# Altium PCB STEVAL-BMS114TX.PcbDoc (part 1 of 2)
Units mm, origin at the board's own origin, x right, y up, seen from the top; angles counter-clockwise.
Board outline 75.8 x 95.1 mm, 4 copper layers (Top Layer, Layer 1, Layer 2, Bottom Layer), stack 1.59 mm thick; 304 components, 148 nets, 694 pads, 400 vias.
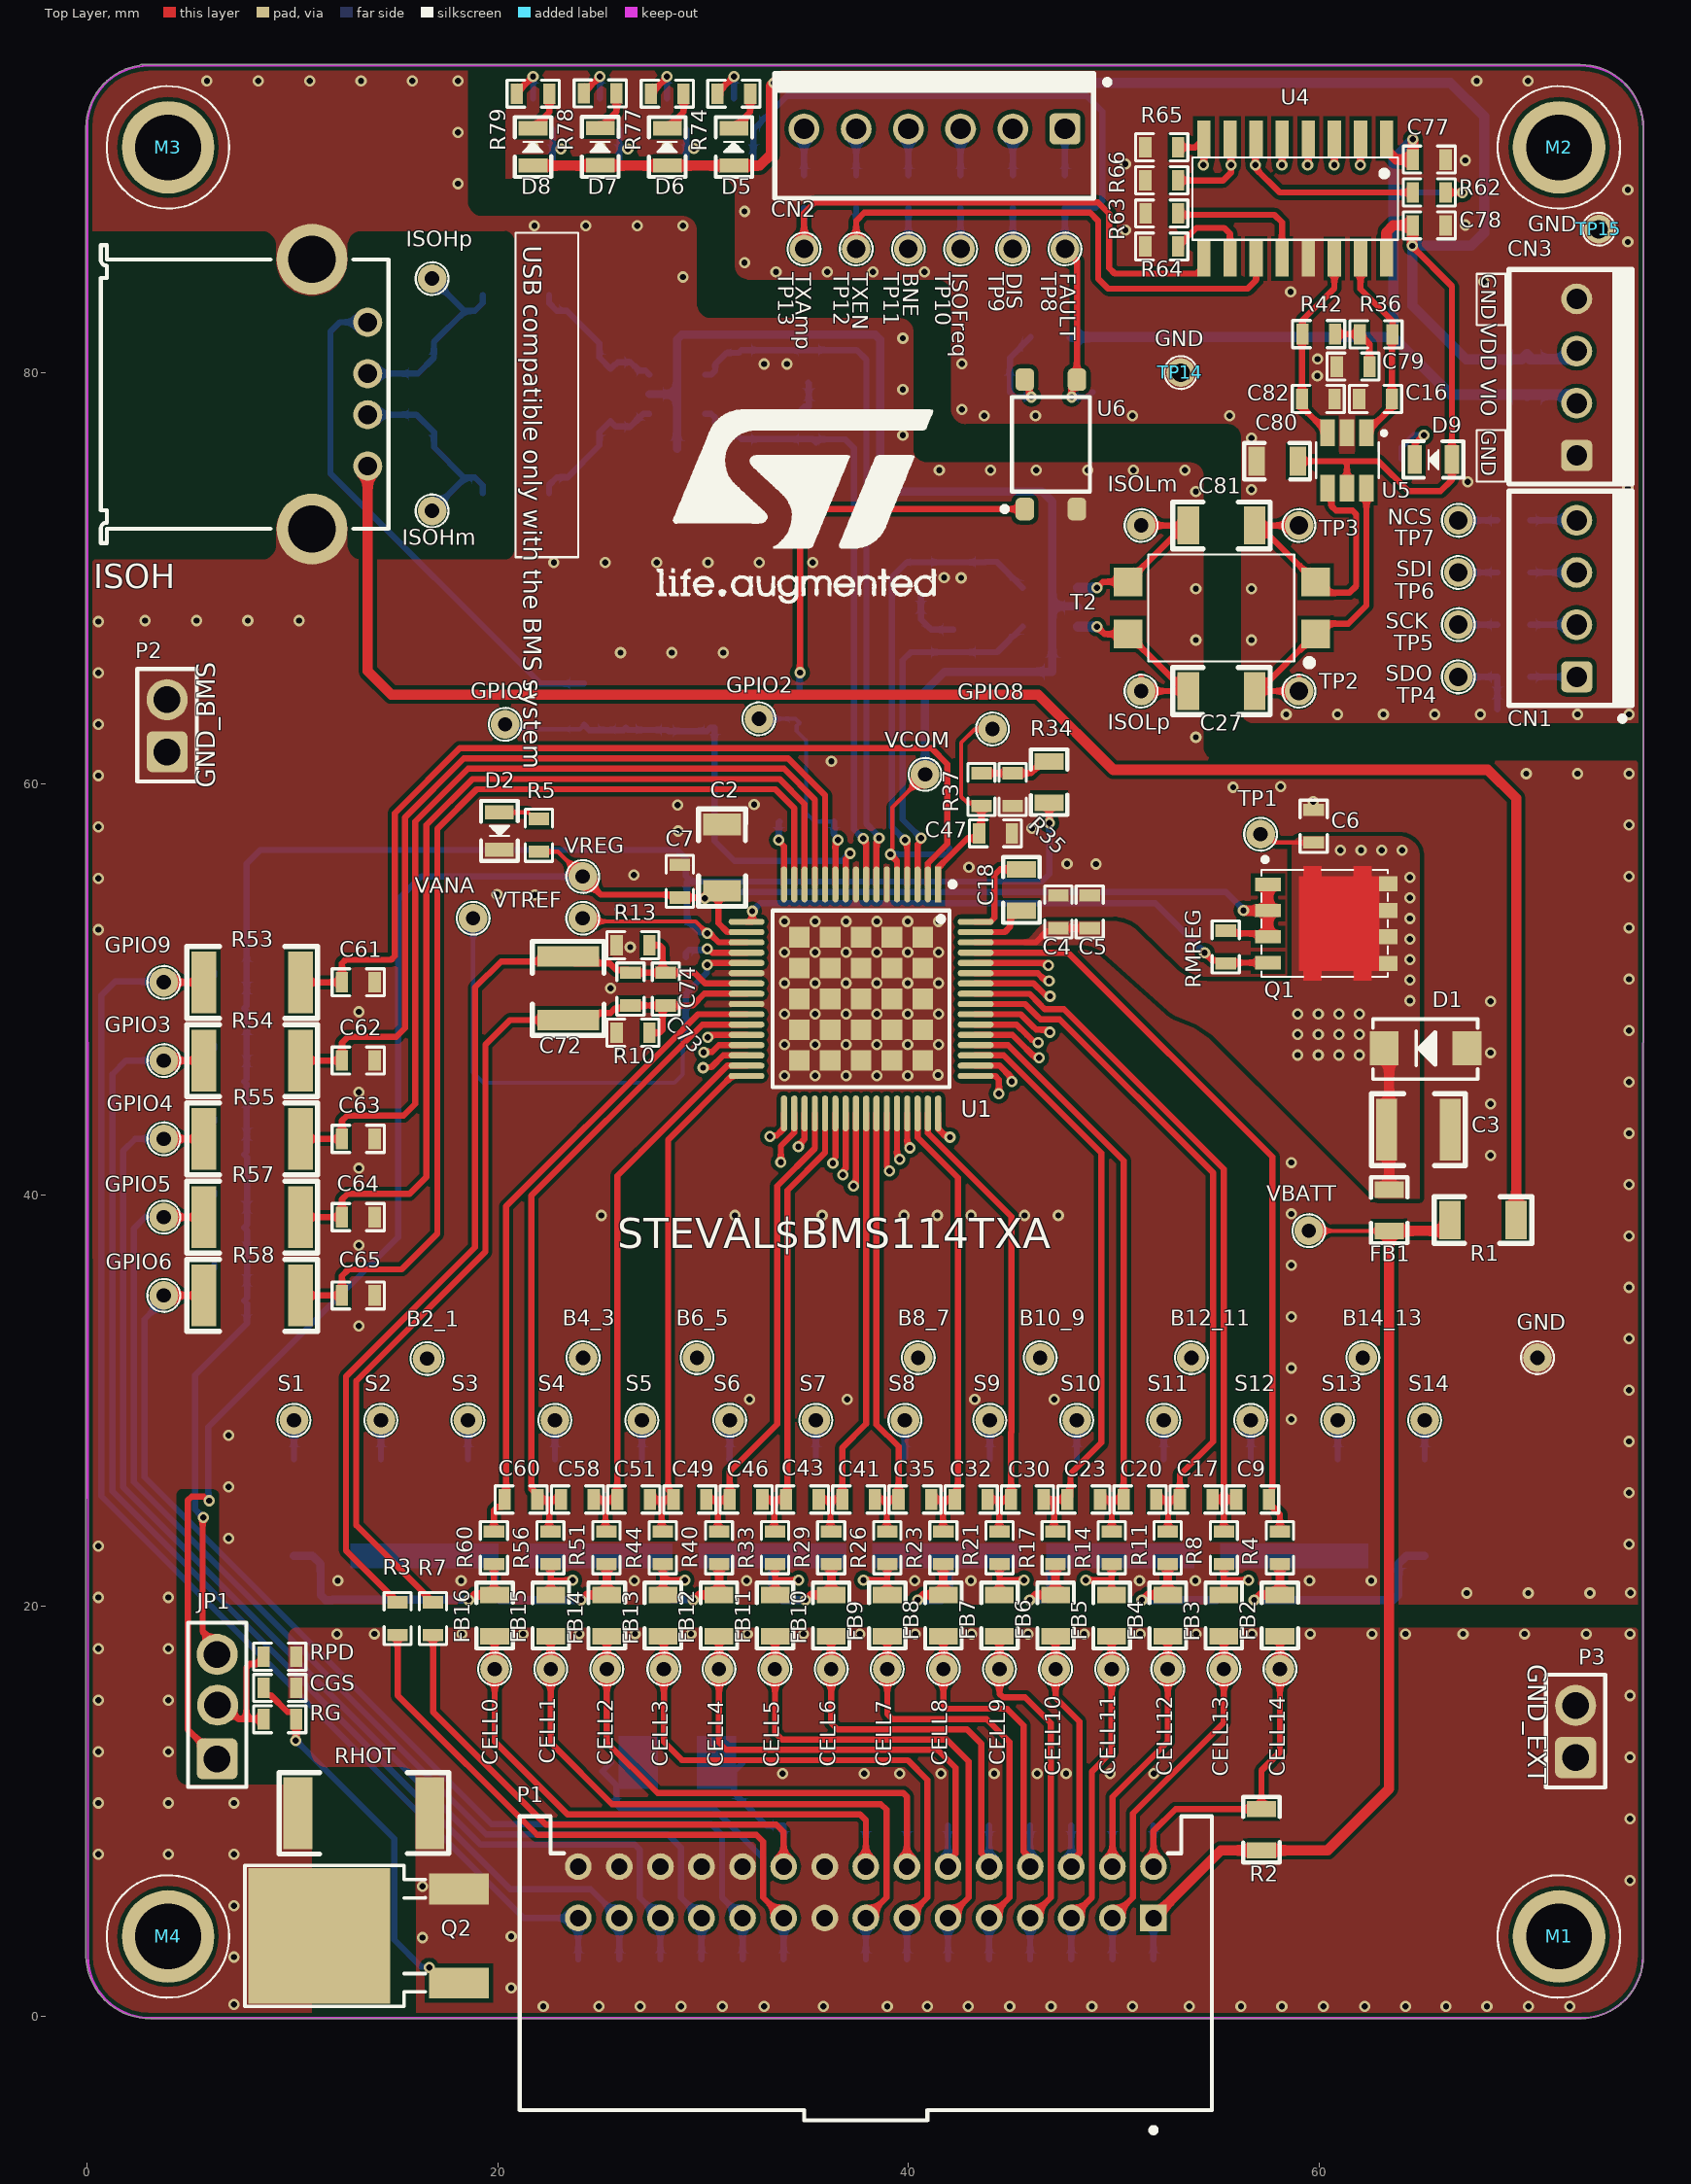
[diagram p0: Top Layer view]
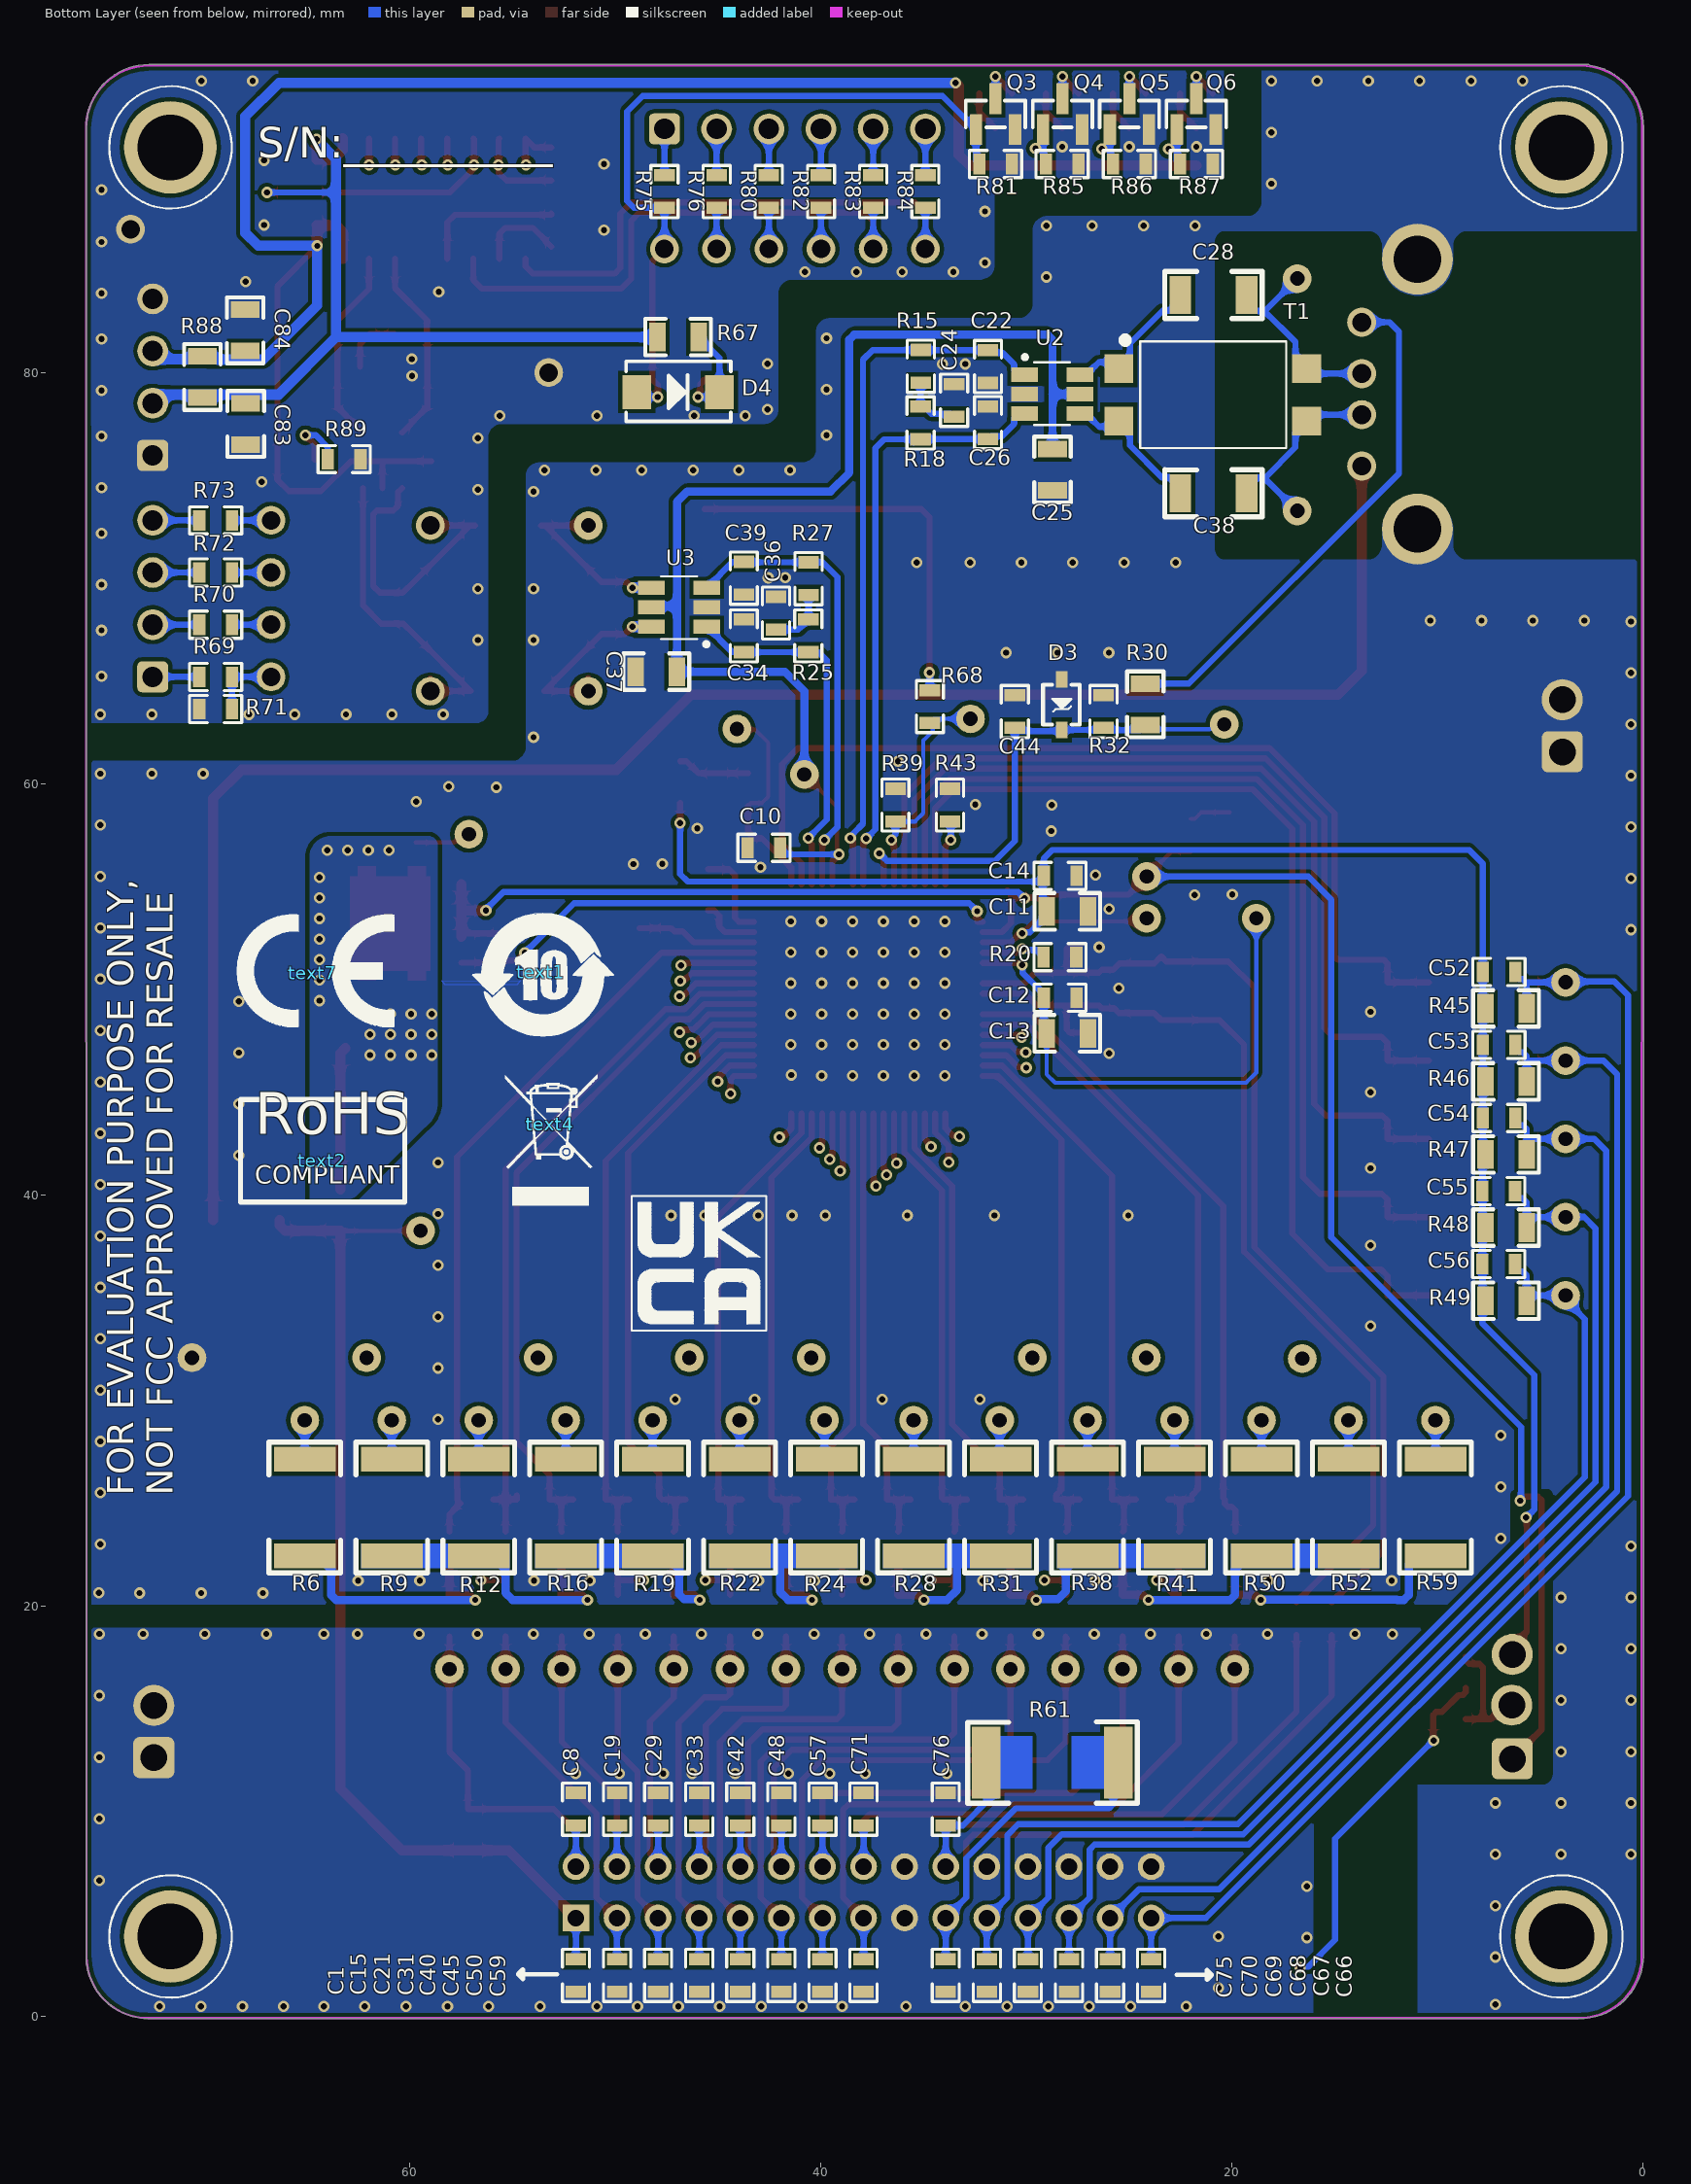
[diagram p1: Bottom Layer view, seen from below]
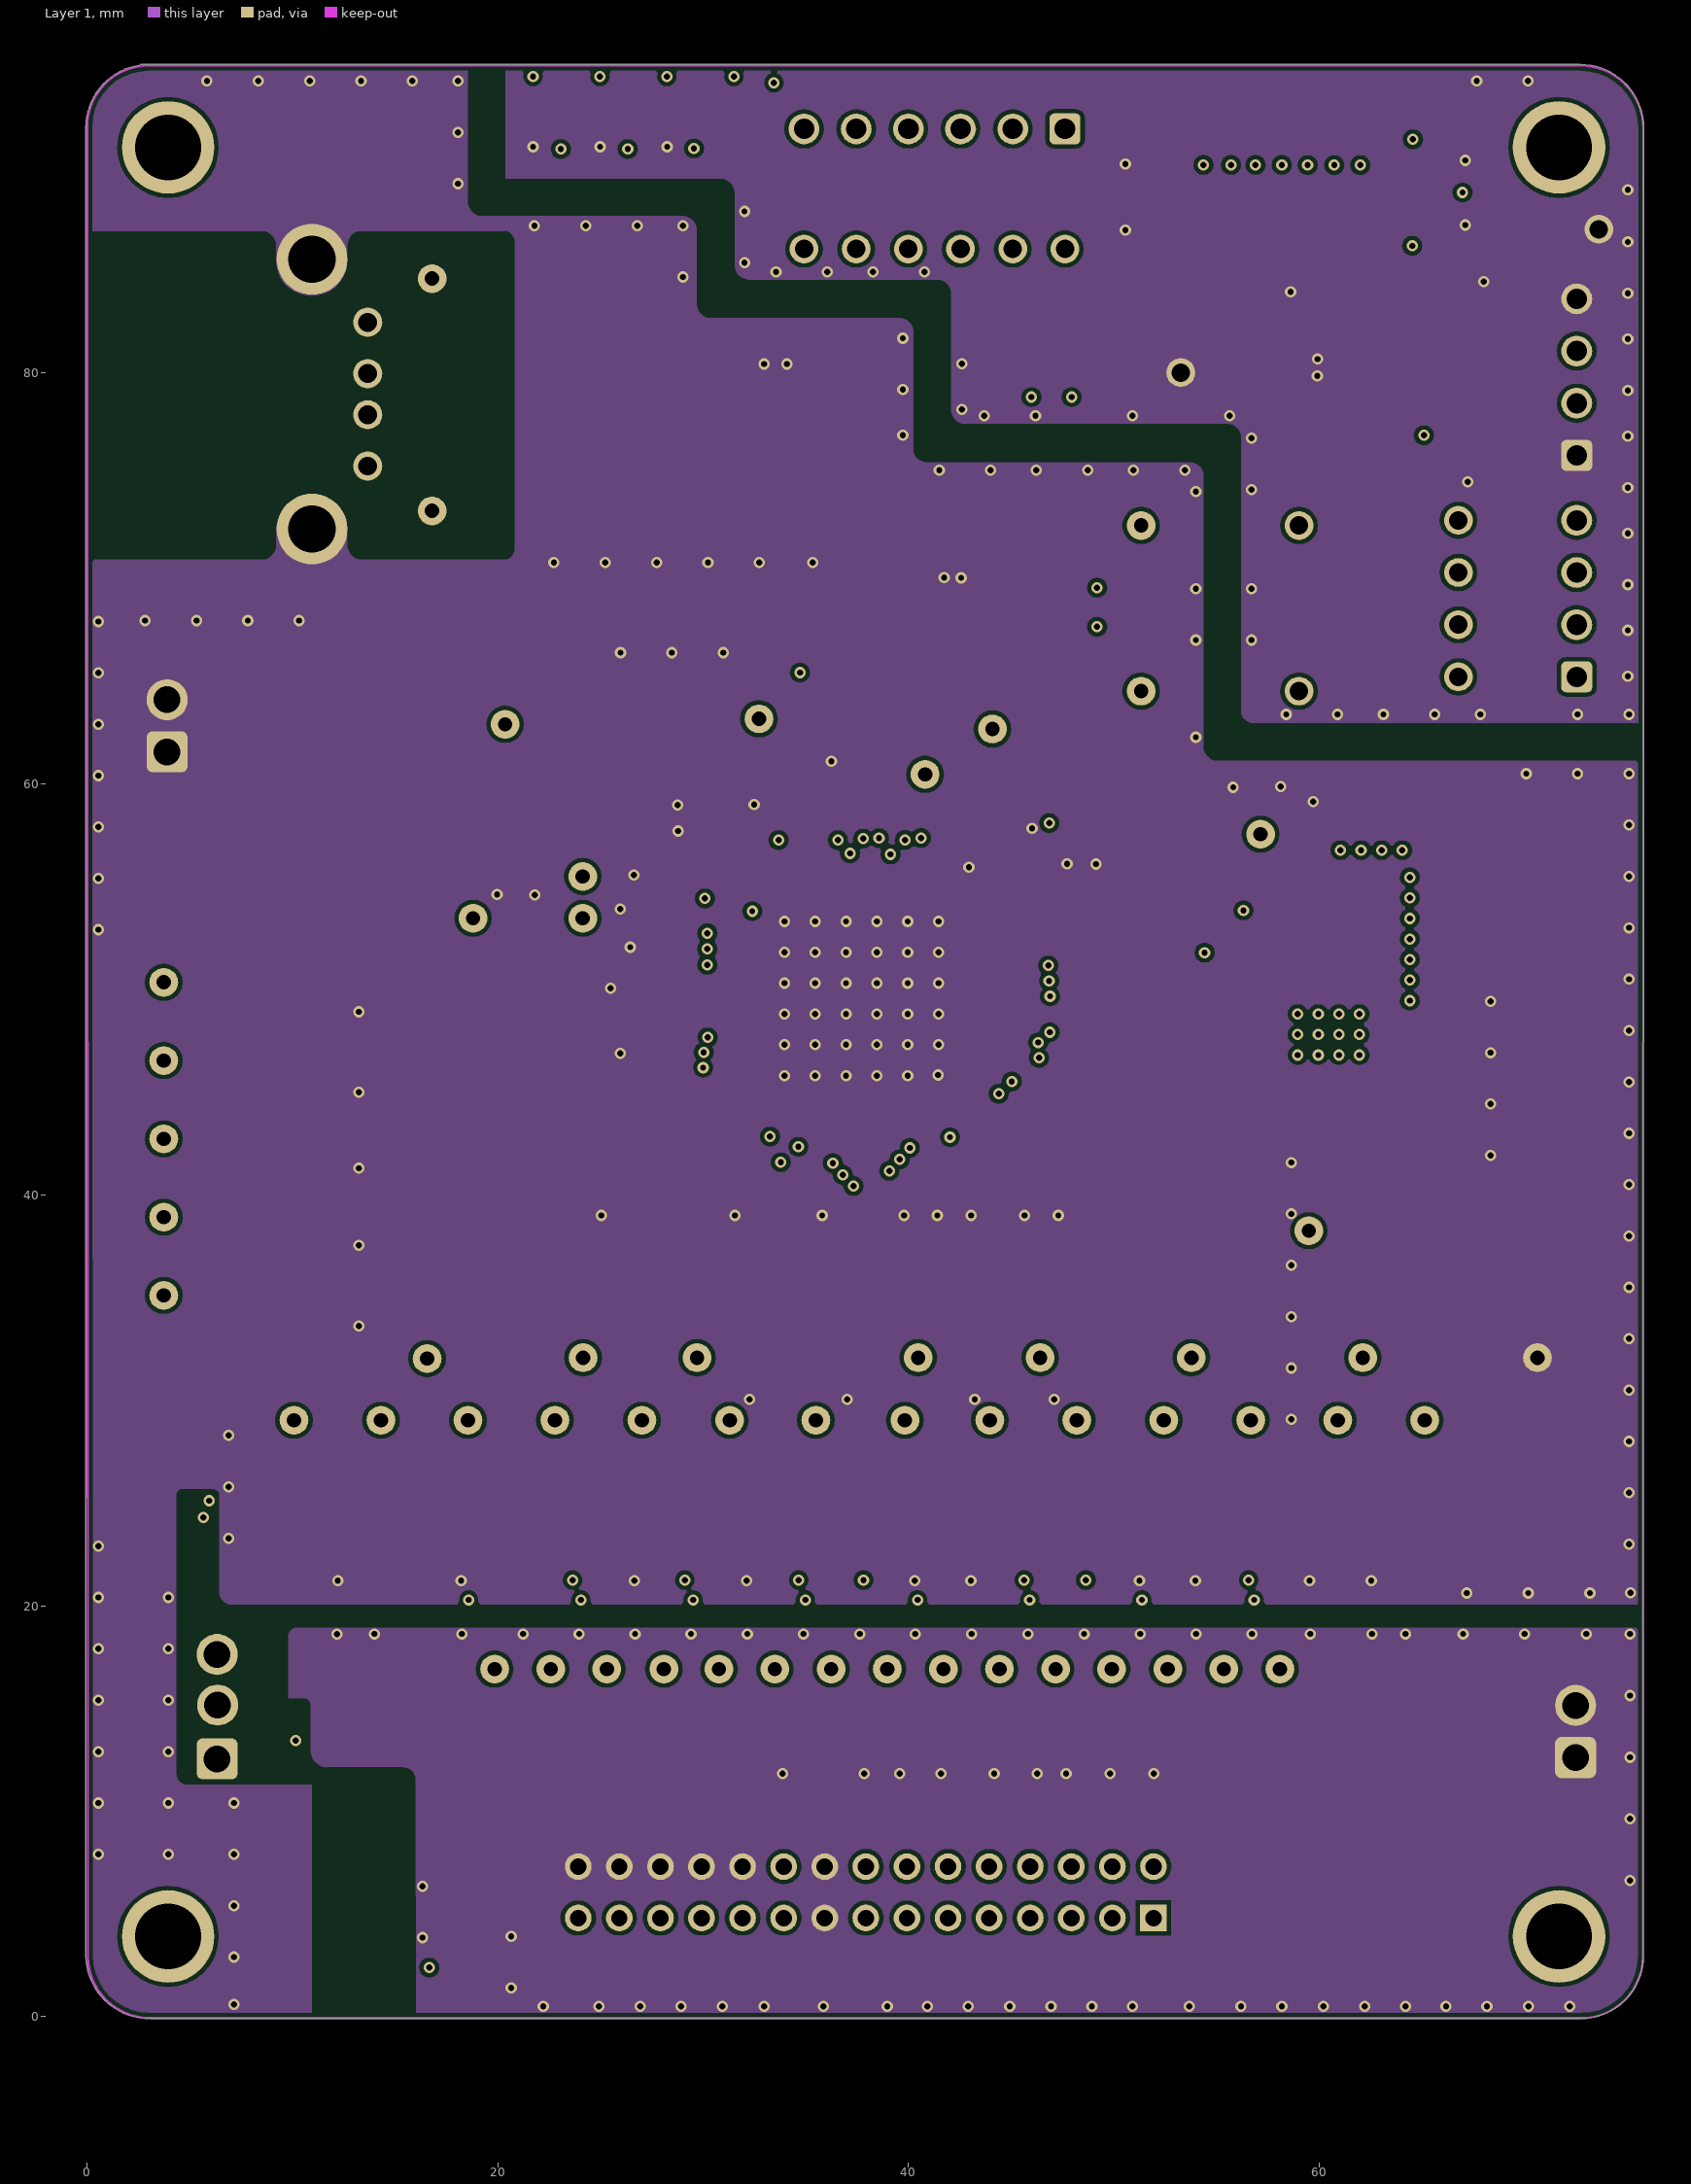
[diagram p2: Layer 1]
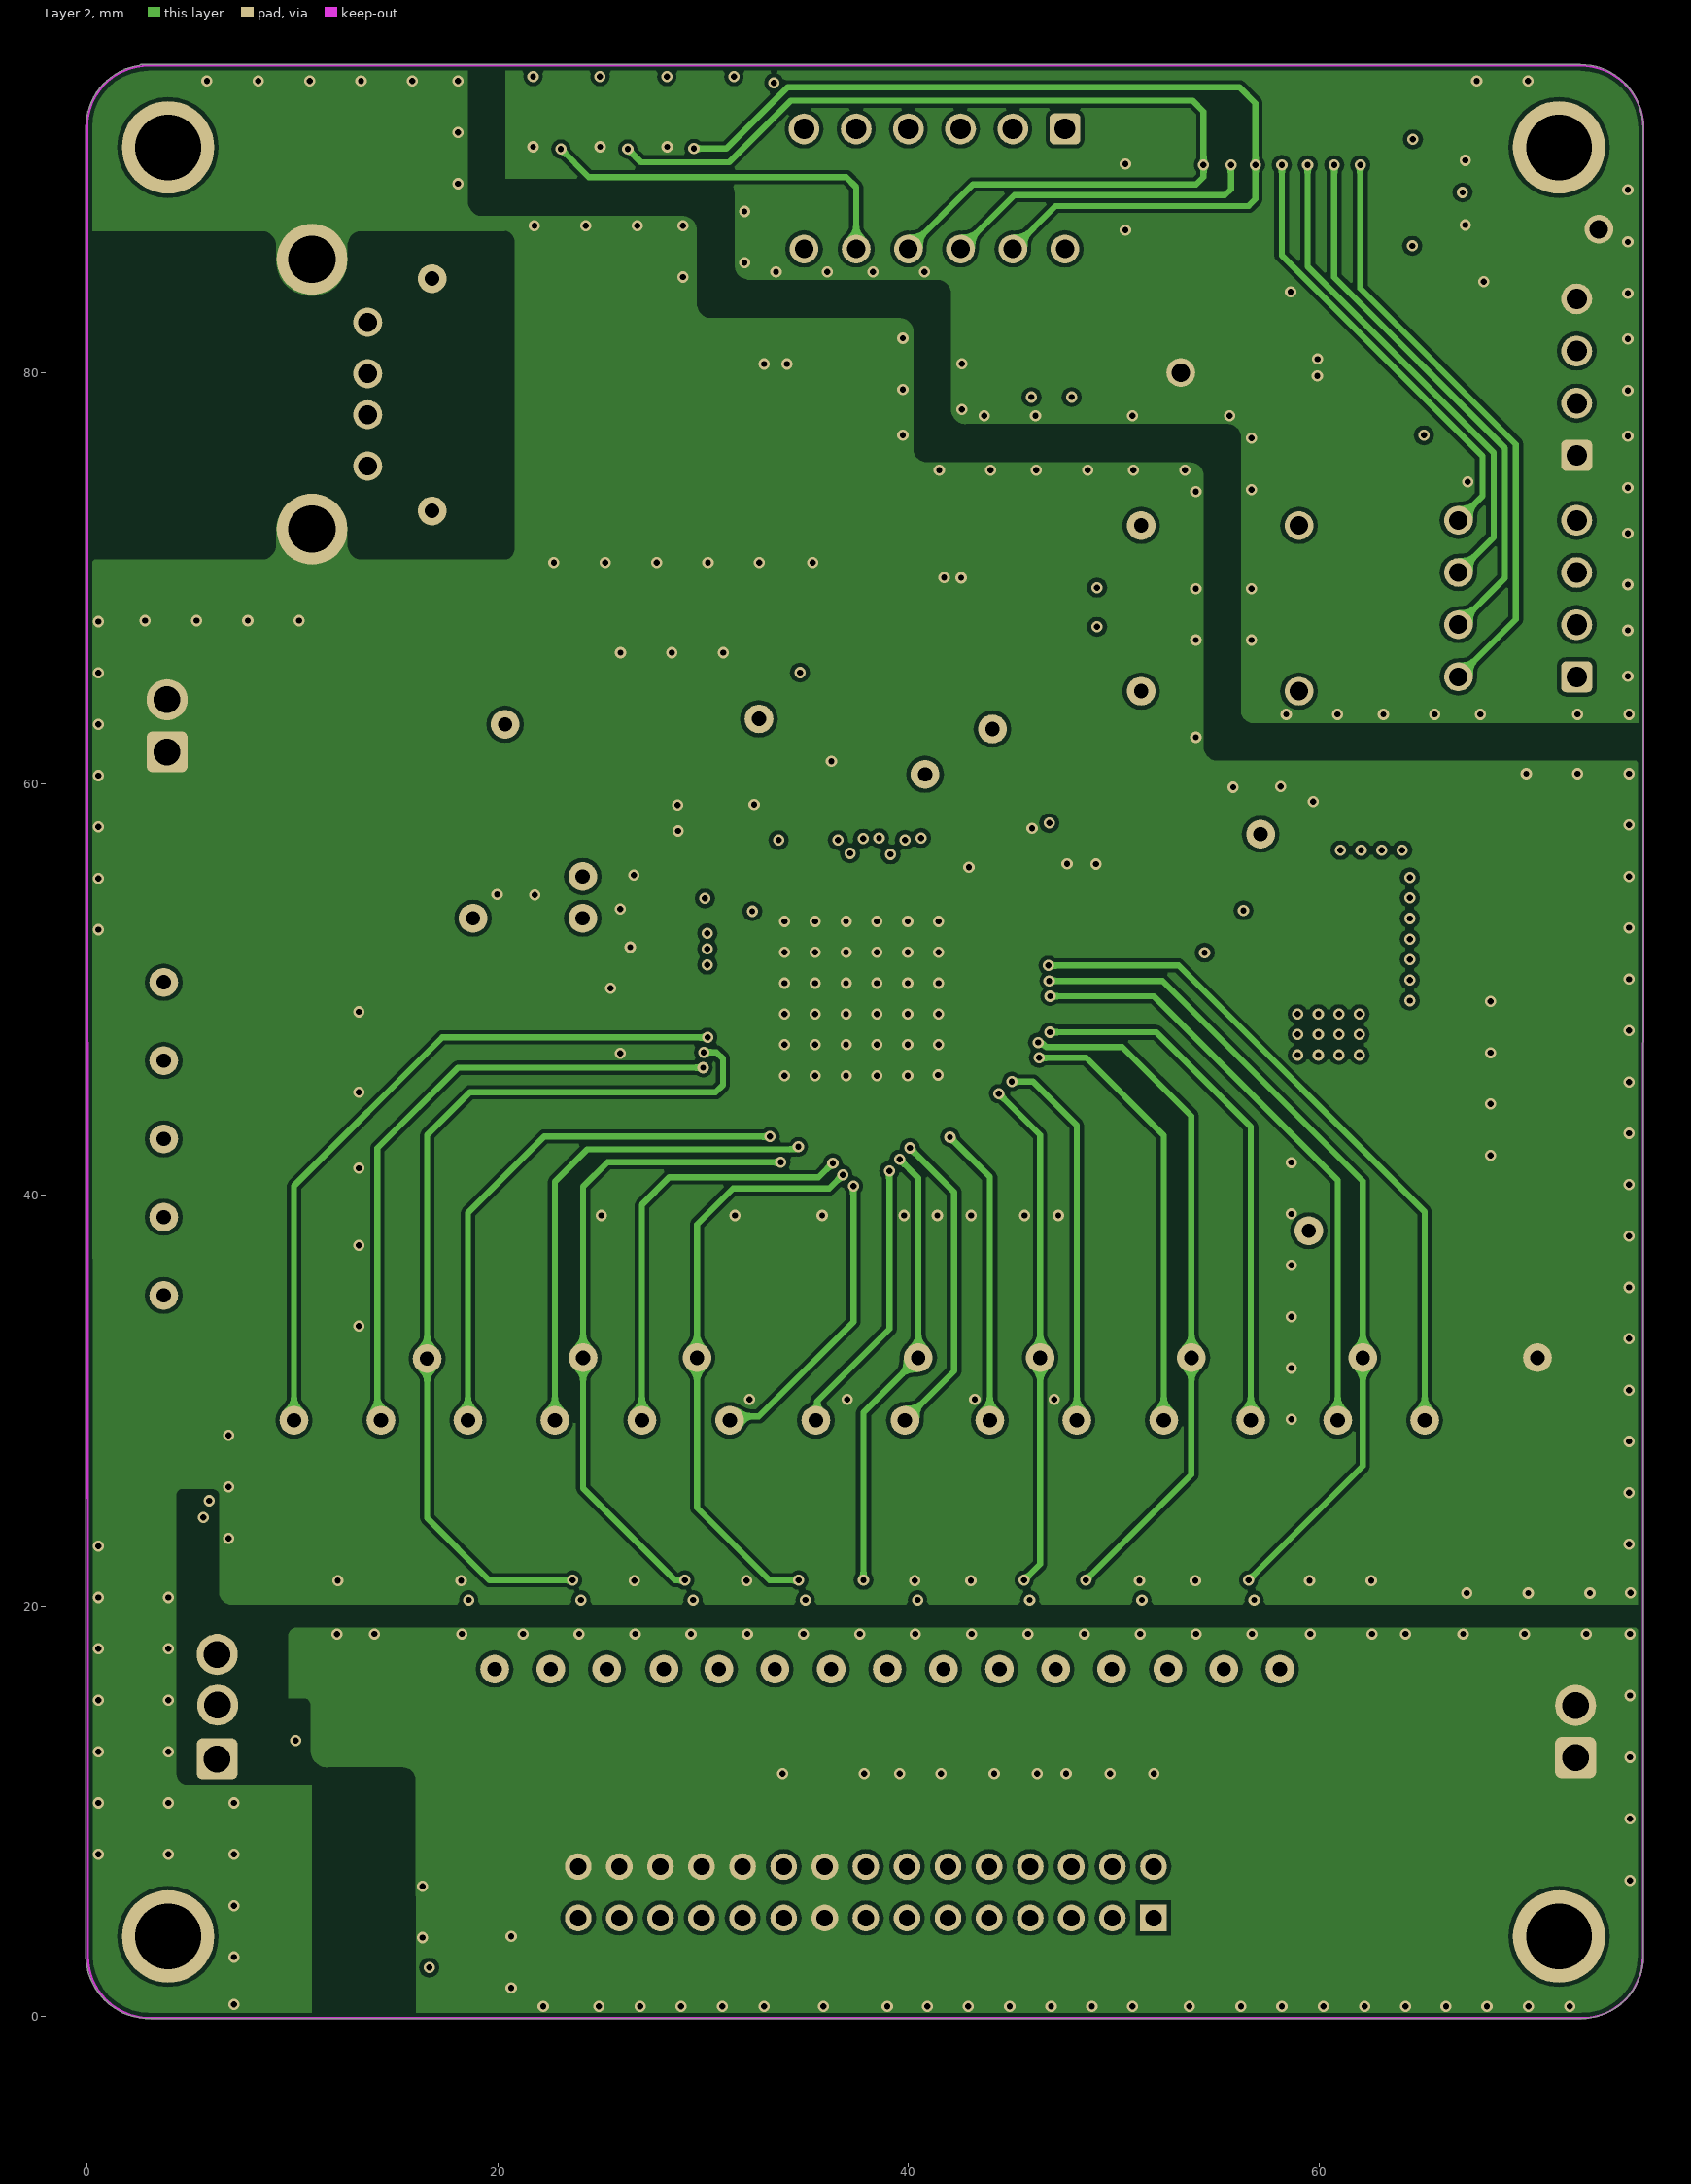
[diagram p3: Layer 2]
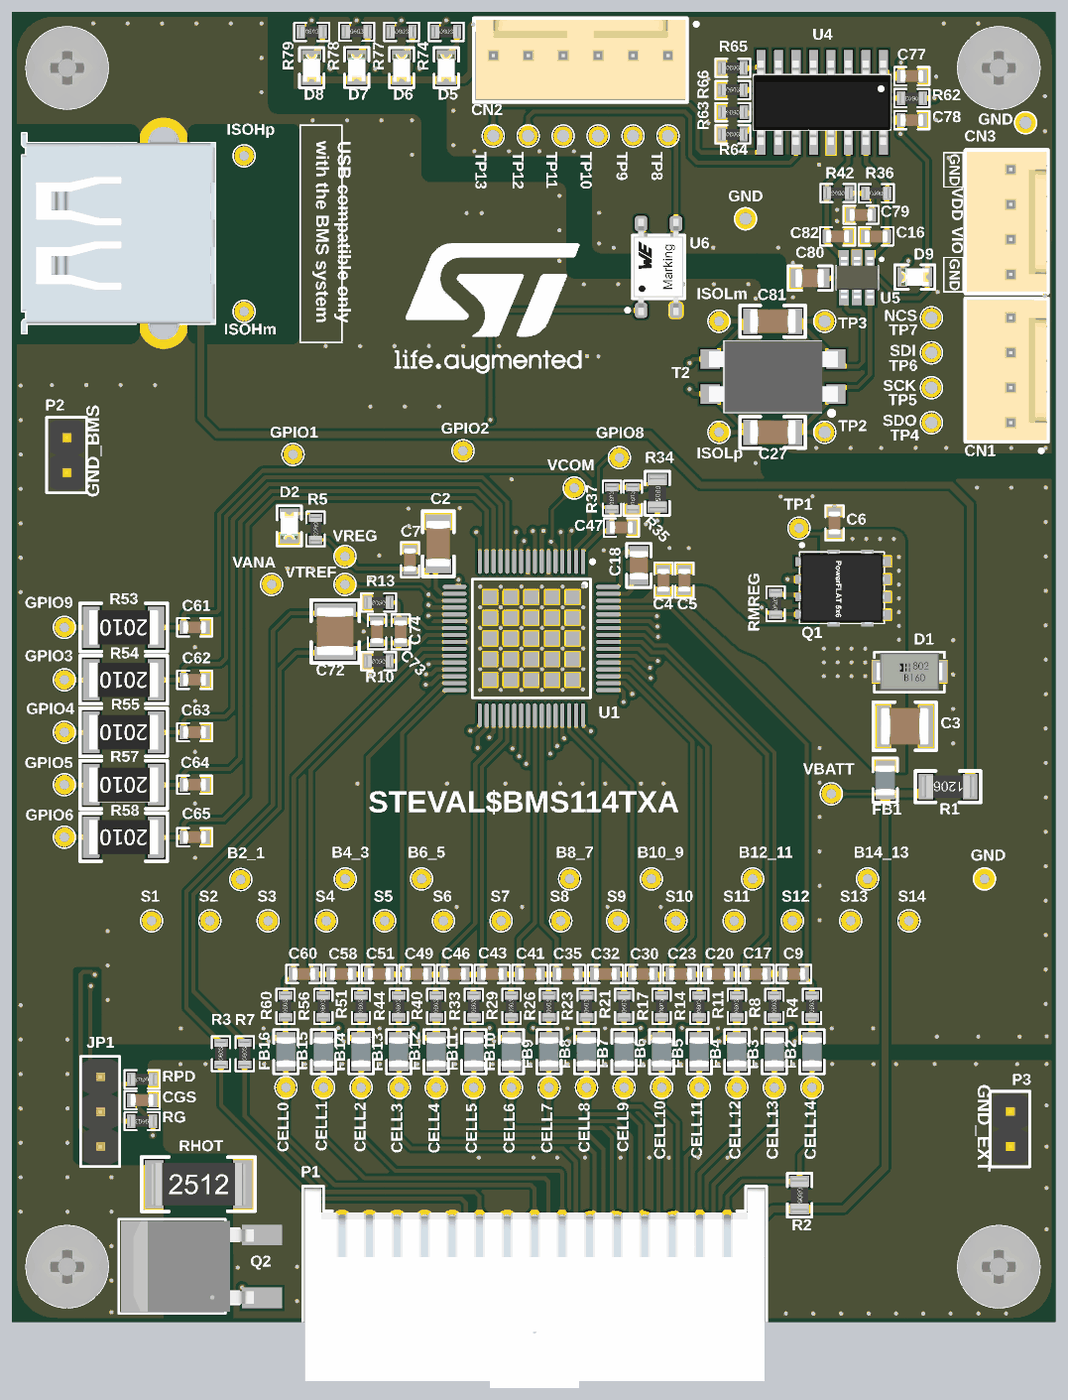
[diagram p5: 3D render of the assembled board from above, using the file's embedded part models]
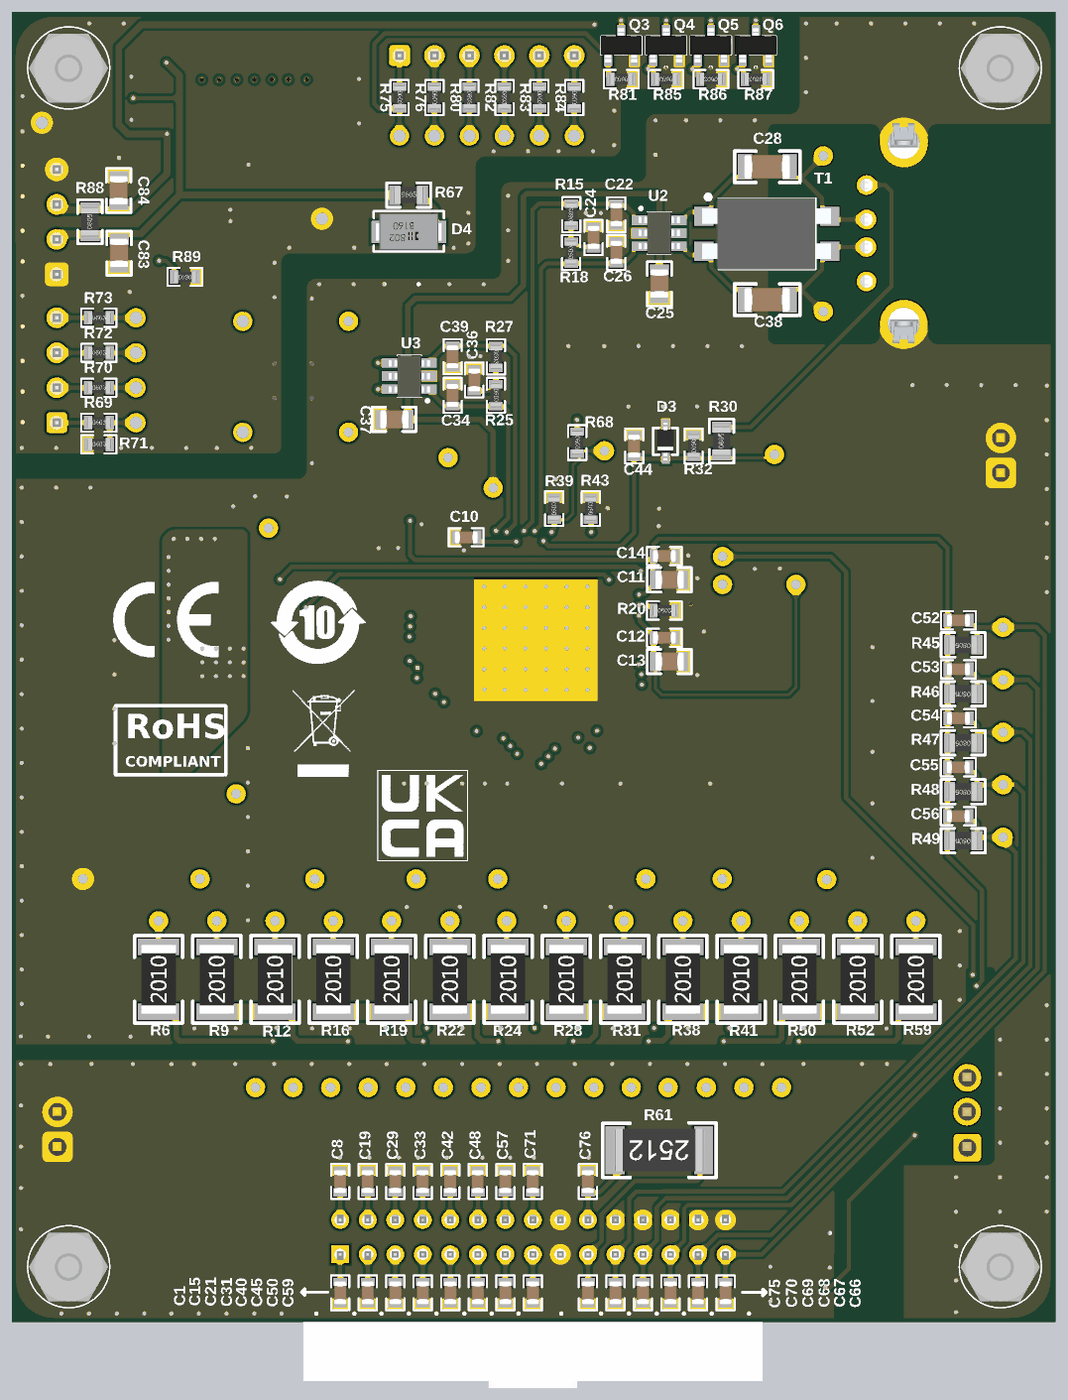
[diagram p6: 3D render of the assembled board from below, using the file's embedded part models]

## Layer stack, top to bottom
Top Solder: solder mask 0.0102, Solder Resist, Dk 3.5
Top Layer: signal copper 0.035
Dielectric 2: prepreg 0.18, PP-006, Dk 4.1
Dielectric 4: prepreg 0.18, PP-006, Dk 4.1
Layer 1: signal copper 0.035
Dielectric 1: dielectric 0.73, FR-4, Dk 4.8
Layer 2: signal copper 0.035
Dielectric 5: prepreg 0.18, PP-006, Dk 4.1
Dielectric 3: prepreg 0.18, PP-006, Dk 4.1
Bottom Layer: signal copper 0.035
Bottom Solder: solder mask 0.0102, Solder Resist, Dk 3.5

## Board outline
-0.038,2.958 -0.038,91.958 -0.038,91.959 cw(c3.012,91.958) 2.572,94.976 2.619,95.008 3.013,95.008 72.713,95.008 cw(c72.713,91.958) 75.763,91.958 75.763,91.957 75.763,2.958 cw(c72.713,2.958) 72.713,-0.092 3.107,-0.092 cw(c3.06,3.005)

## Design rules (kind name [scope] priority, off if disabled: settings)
Clearance [All] p1: gap=0.2 ignorepadtopadclearanceinfootprint=FALSE
ComponentClearance [All] p1: gap=0.1 collisioncheckmode=3 verticalgap=0.254 showdistances=FALSE
MinimumSolderMaskSliver [All] p1: minsoldermaskwidth=0.1
PolygonConnect [All] p1: connectstyle=Direct reliefconductorwidth=0.254 reliefentries=4 polygonreliefangle="90 Angle" airgapwidth=0.254
RoutingVias [All] p1: holewidth=0.711 width=1.27 viastyle="Through Hole" minholewidth=0.711 minwidth=1.27 maxholewidth=0.711 maxwidth=1.27
SilkToSilkClearance [All] p1 off: silktosilkclearance=0.05
SilkToSolderMaskClearance [IsPad] p1 off: minsilkscreentomaskgap=0.05 clearancetoexposedcopper=TRUE
SolderMaskExpansion [All] p1: expansion=0.102 istentingtop=FALSE
Width [All] p1: maxlimit=1 minlimit=0.15 preferedwidth=0.2
26 further rules are at their usual default settings.

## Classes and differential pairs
component class "[2]AEK-POW-BMSWTX_Isolated SPI & MCU interface": C16 C27 C77 C78 C79 C80 C81 C82 C83 C84 CN1 CN2 CN3 D4 D5 D6 D7 D8 D9 ISOLm ISOLp Q3 Q4 Q5 Q6 R36 R42 R62 R63 R64 R65 R66 R67 R68 R69 R70 R71 R72 R73 R74 R75 R76 R77 R78 R79 R80 R81 R82 R83 R84 R85 R86 R87 R88 R89 T2 TP2 TP3 TP4 TP5 TP6 TP7 TP8 TP9 TP10 TP11 TP12 TP13 TP14 TP15 U4 U5 U6
component class [3]Loghi: M1 M2 M3 M4 text1 text2 text3 text4 text7 text9
component class "[1]AEK-POW-BMSWTX_BMS Node": B2_1 B4_3 B6_5 B8_7 B10_9 B12_11 B14_13 C0 C1 C2 C3 C4 C5 C6 C7 C8 C9 C10 C11 C12 C13 C14 C15 C17 C18 C19 C20 C21 C22 C23 C24 C25 C26 C28 C29 C30 C31 C32 C33 C34 C35 C36 C37 C38 C39 C40 C41 C42 C43 C44 C45 C46 C47 C48 C49 C50 C51 C52 C53 C54 C55 C56 C57 C58 C59 C60 C61 C62 C63 C64 C65 C66 C67 C68 C69 C70 C71 C72 C73 C74 C75 C76 CELL0 CELL1 CELL2 CELL3 CELL4 CELL5 CELL6 CELL7 CELL8 CELL9 CELL10 CELL11 CELL12 CELL13 CELL14 CGS D1 D2 D3 FB1 FB2 FB3 FB4 FB5 FB6 FB7 FB8 FB9 FB10 FB11 FB12 FB13 FB14 FB15 FB16 GND GPIO1 GPIO2 GPIO3 GPIO4 GPIO5 GPIO6 GPIO8 GPIO9 ISOH ISOHm ISOHp JP1 P1 P2 P3 Q1 Q2 R1 R2 R3 R4 R5 R6 R7 R8 R9 R10 R11 R12 R13 R14 R15 R16 R17 R18 R19 R20 R21 R22 R23 R24 R25 R26 R27 R28 R29 R30 R31 R32 R33 R34 R35 R37 R38 R39 R40 R41 R43 R44 R45 R46 R47 R48 R49 R50 R51 R52 R53 R54 R55 R56 R57 R58 R59 R60 R61 RG RHOT RMREG RPD S1 S2 S3 S4 S5 S6 S7 S8 S9 S10 S11 S12 S13 S14 T1 TP1 U1 U2 U3 VANA VBATT VCOM VREG VTREF

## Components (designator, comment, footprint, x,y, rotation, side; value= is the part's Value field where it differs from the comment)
B2_1 "TEST POINT_TH" TP_0.7mm 16.568,32.027 r90 top
B4_3 "TEST POINT_TH" TP_0.7mm 24.162,32.07 r90 top
B6_5 "TEST POINT_TH" TP_0.7mm 29.706,32.07 r90 top
B8_7 "TEST POINT_TH" TP_0.7mm 40.474,32.07 r90 top
B10_9 "TEST POINT_TH" TP_0.7mm 46.408,32.07 r90 top
B12_11 "TEST POINT_TH" TP_0.7mm 53.769,32.07 r90 top
B14_13 "TEST POINT_TH" TP_0.7mm 62.113,32.07 r90 top
C1 "Capacitor_0603" 0603C 51.924,1.21 r90 bottom value=47nF
C2 "Capacitor_1206" 1206C 30.927,58.028 r270 top value=4.7uF
C3 "Capacitor_1210" 1210C 66.372,43.165 r180 top value=2.2uF
C4 "Capacitor_0603" 0603C 47.296,54.571 r270 top value=100nF
C5 "Capacitor_0603" 0603C 48.817,54.571 r270 top value=100pF
C6 "Capacitor_0603" 0603C 59.722,58.738 r270 top value=100nF
C7 "100nF" 0603C 28.871,56.057 r270 top value=N.M.
C8 "Capacitor_0603" 0603C 51.924,10.896 r270 bottom value=47nF
C9 "Capacitor_0603" 0603C 55.949,25.173 r0 top value=10nF
C10 "Capacitor_0603" 0603C 43.573,56.889 r180 bottom value=220nF
C11 "Capacitor_0805" 0805C 27,53.799 r0 bottom value=2.2uF
C12 "100nF" 0603C 27.562,49.588 r0 bottom value=N.M.
C13 "Capacitor_0805" 0805C 27,47.863 r0 bottom value=2.2uF
C14 "Capacitor_0603" 0603C 27.562,55.524 r0 bottom value=100nF
C15 "Capacitor_0603" 0603C 49.924,1.21 r90 bottom value=47nF
C16 "Cap 22pF" 0603C 61.935,78.738 r0 top value=22pF
C17 "Capacitor_0603" 0603C 53.21,25.173 r0 top value=10nF
C18 "Capacitor_0805" 0805C 45.498,55.845 r270 top value=1uF
C19 "Capacitor_0603" 0603C 49.924,10.896 r270 bottom value=47nF
C20 "Capacitor_0603" 0603C 50.471,25.173 r0 top value=10nF
C21 "Capacitor_0603" 0603C 47.924,1.21 r90 bottom value=47nF
C22 "Capacitor_0603" 0603C 31.866,79.516 r90 bottom value=22pF
C23 "Capacitor_0603" 0603C 47.732,25.173 r0 top value=10nF
C24 "Capacitor_0603" 0603C 33.517,77.865 r90 bottom value=10nF
C25 "Capacitor_0805" 0805C 28.727,76.306 r270 bottom value=1uF
C26 "Capacitor_0603" 0603C 31.866,76.78 r90 bottom value=22pF
C27 "47nF" 1206C 56.844,64.515 r180 top value=N.M.
C28 "47nF" 1206C 22.504,83.798 r180 bottom value=N.M.
C29 "Capacitor_0603" 0603C 47.924,10.896 r270 bottom value=47nF
C30 "Capacitor_0603" 0603C 44.993,25.173 r0 top value=10nF
C31 "Capacitor_0603" 0603C 45.924,1.21 r90 bottom value=47nF
C32 "Capacitor_0603" 0603C 42.254,25.173 r0 top value=10nF
C33 "Capacitor_0603" 0603C 45.924,10.896 r270 bottom value=47nF
C34 "Capacitor_0603" 0603C 43.754,68.002 r270 bottom value=22pF
C35 "Capacitor_0603" 0603C 39.515,25.173 r0 top value=10nF
C36 "Capacitor_0603" 0603C 42.183,67.511 r90 bottom value=10nF
C37 "Capacitor_0805" 0805C 47.003,65.461 r0 bottom value=1uF
C38 "47nF" 1206C 22.504,74.146 r180 bottom value=N.M.
C39 "Capacitor_0603" 0603C 43.754,70.808 r270 bottom value=22pF
C40 "Capacitor_0603" 0603C 43.924,1.21 r90 bottom value=47nF
C41 "Capacitor_0603" 0603C 36.777,25.173 r0 top value=10nF
C42 "Capacitor_0603" 0603C 43.924,10.896 r270 bottom value=47nF
C43 "Capacitor_0603" 0603C 34.038,25.173 r0 top value=10nF
C44 "Capacitor_0603" 0603C 30.56,64.318 r270 bottom value=2.2nF
C45 "Capacitor_0603" 0603C 41.924,1.21 r90 bottom value=47nF
C46 "Capacitor_0603" 0603C 31.299,25.173 r0 top value=10nF
C47 "Capacitor_0603" 0603C 45.032,57.596 r180 top value=6.8nF
C48 "Capacitor_0603" 0603C 41.924,10.896 r270 bottom value=47nF
C49 "Capacitor_0603" 0603C 28.56,25.173 r0 top value=10nF
C50 "Capacitor_0603" 0603C 39.924,1.21 r90 bottom value=47nF
C51 "Capacitor_0603" 0603C 25.822,25.173 r0 top value=10nF
C52 "Capacitor_0603" 0603C 6.19,50.851 r0 bottom value=100nF
C53 "Capacitor_0603" 0603C 6.19,47.295 r0 bottom value=100nF
C54 "Capacitor_0603" 0603C 6.19,43.739 r0 bottom value=100nF
C55 "Capacitor_0603" 0603C 6.206,40.18 r0 bottom value=100nF
C56 "Capacitor_0603" 0603C 6.206,36.628 r0 bottom value=100nF
C57 "Capacitor_0603" 0603C 39.924,10.896 r270 bottom value=47nF
C58 "Capacitor_0603" 0603C 23.084,25.173 r0 top value=10nF
C59 "Capacitor_0603" 0603C 37.924,1.21 r90 bottom value=47nF
C60 "Capacitor_0603" 0603C 20.346,25.173 r0 top value=10nF
C61 "Capacitor_0603" 0603C 14.014,50.343 r180 top value=2.2nF
C62 "Capacitor_0603" 0603C 14.014,46.533 r180 top value=2.2nF
C63 "Capacitor_0603" 0603C 14.014,42.723 r180 top value=2.2nF
C64 "Capacitor_0603" 0603C 14.014,38.913 r180 top value=2.2nF
C65 "Capacitor_0603" 0603C 14.014,35.103 r180 top value=2.2nF
C66 "Capacitor_0603" 0603C 23.924,1.21 r90 bottom value=6.8nF
C67 "Capacitor_0603" 0603C 25.924,1.21 r90 bottom value=6.8nF
C68 "Capacitor_0603" 0603C 27.924,1.21 r90 bottom value=6.8nF
C69 "Capacitor_0603" 0603C 29.924,1.21 r90 bottom value=6.8nF
C70 "Capacitor_0603" 0603C 31.924,1.21 r90 bottom value=6.8nF
C71 "Capacitor_0603" 0603C 37.924,10.896 r270 bottom value=47nF
C72 "Capacitor_1210" 1210C 23.431,48.504 r90 top value=10uF
C73 "Capacitor_0603" 0603C 26.465,49.217 r90 top value=68nF
C74 "Capacitor_0603" 0603C 28.19,49.217 r90 top value=33pF
C75 "Capacitor_0603" 0603C 33.924,1.21 r90 bottom value=47nF
C76 "Capacitor_0603" 0603C 33.924,10.896 r270 bottom value=47nF
C77 "Capacitor_0603" 0603C 66.148,90.385 r180 top value=100nF
C78 "Capacitor_0603" 0603C 66.148,87.185 r180 top value=100nF
C79 "Cap 10nF" 0603C 60.843,80.309 r0 top value=10nF
C80 "Cap 1uF_1" 0805C 56.939,75.706 r0 top value=1uF
C81 "47nF" 1206C 56.844,72.578 r180 top value=N.M.
C82 "Cap 22pF" 0603C 60.747,78.738 r180 top value=22pF
C83 "Cap 1uF_1" 0805C 67.995,78.527 r270 bottom value=1uF
C84 "Cap 1uF_1" 0805C 68.029,83.08 r270 bottom value=1uF
CELL0 "TEST POINT_TH" TP_0.7mm 19.854,16.921 r90 top
CELL1 "TEST POINT_TH" TP_0.7mm 22.585,16.921 r90 top
CELL2 "TEST POINT_TH" TP_0.7mm 25.315,16.921 r90 top
CELL3 "TEST POINT_TH" TP_0.7mm 28.091,16.921 r90 top
CELL4 "TEST POINT_TH" TP_0.7mm 30.776,16.921 r90 top
CELL5 "TEST POINT_TH" TP_0.7mm 33.493,16.921 r90 top
CELL6 "TEST POINT_TH" TP_0.7mm 36.237,16.921 r90 top
CELL7 "TEST POINT_TH" TP_0.7mm 38.968,16.921 r90 top
CELL8 "TEST POINT_TH" TP_0.7mm 41.698,16.921 r90 top
CELL9 "TEST POINT_TH" TP_0.7mm 44.429,16.921 r90 top
CELL10 "TEST POINT_TH" TP_0.7mm 47.159,16.921 r90 top
CELL11 "TEST POINT_TH" TP_0.7mm 49.89,16.921 r90 top
CELL12 "TEST POINT_TH" TP_0.7mm 52.62,16.921 r90 top
CELL13 "TEST POINT_TH" TP_0.7mm 55.351,16.921 r90 top
CELL14 "TEST POINT_TH" TP_0.7mm 58.081,16.921 r90 top
CGS "Capacitor_0603" 0603C 10.196,15.999 r180 top value=4.7nF
CN1 "Con 4P" KK254_4p 72.528,65.208 r270 top
CN2 "Con 6P" KK254_6P 47.615,91.881 r0 top
CN3 "Con 4P" KK254_4p 72.528,75.987 r270 top
D1 "SMA6T68AY" SMA 67.185,47.132 r0 top
D2 "LED_Green" LED_0805 20.088,58.612 r90 top value=Green
D3 "SZMM3Z4V7T1G" SOD-323 28.27,65.08 r90 bottom
D4 "SMA6T68AY" SMA 48.96,79.068 r0 bottom
D5 "LED_Red" LED_0805 31.504,90.095 r270 top value=Red
D6 "LED_Amber" LED_0805 28.257,90.095 r270 top value=Amber
D7 "LED_Yellow" LED_0805 24.994,90.105 r270 top value=Yellow
D8 "LED_Blue" LED_0805 21.726,90.095 r270 top value=Blue
D9 "LED_Green" LED_0805 66.453,75.787 r0 top value=Green
FB1 "MPZ2012S102ATD25" 0805L 63.399,38.245 r90 top value=1K@100MHz
FB2 "MPZ2012S102ATD25" 0805L 58.081,18.516 r90 top value=1K@100MHz
FB3 "MPZ2012S102ATD25" 0805L 55.351,18.516 r90 top value=1K@100MHz
FB4 "MPZ2012S102ATD25" 0805L 52.62,18.516 r90 top value=1K@100MHz
FB5 "MPZ2012S102ATD25" 0805L 49.89,18.516 r90 top value=1K@100MHz
FB6 "MPZ2012S102ATD25" 0805L 47.159,18.516 r90 top value=1K@100MHz
FB7 "MPZ2012S102ATD25" 0805L 44.429,18.516 r90 top value=1K@100MHz
FB8 "MPZ2012S102ATD25" 0805L 41.698,18.516 r90 top value=1K@100MHz
FB9 "MPZ2012S102ATD25" 0805L 38.968,18.516 r90 top value=1K@100MHz
FB10 "MPZ2012S102ATD25" 0805L 36.237,18.516 r90 top value=1K@100MHz
FB11 "MPZ2012S102ATD25" 0805L 33.507,18.516 r90 top value=1K@100MHz
FB12 "MPZ2012S102ATD25" 0805L 30.776,18.516 r90 top value=1K@100MHz
FB13 "MPZ2012S102ATD25" 0805L 28.046,18.516 r90 top value=1K@100MHz
FB14 "MPZ2012S102ATD25" 0805L 25.315,18.516 r90 top value=1K@100MHz
FB15 "MPZ2012S102ATD25" 0805L 22.585,18.516 r90 top value=1K@100MHz
FB16 "MPZ2012S102ATD25" 0805L 19.854,18.516 r90 top value=1K@100MHz
GND "TEST POINT_TH" TP_0.7mm 70.617,32.07 r90 top
GPIO1 "TEST POINT_TH" TP_0.7mm 20.364,62.901 r90 top
GPIO2 "TEST POINT_TH" TP_0.7mm 32.721,63.167 r90 top
GPIO3 "TEST POINT_TH" TP_0.7mm 3.75,46.533 r0 top
GPIO4 "TEST POINT_TH" TP_0.7mm 3.75,42.723 r0 top
GPIO5 "TEST POINT_TH" TP_0.7mm 3.75,38.913 r0 top
GPIO6 "TEST POINT_TH" TP_0.7mm 3.75,35.103 r0 top
GPIO8 "TEST POINT_TH" TP_0.7mm 44.085,62.672 r90 top
GPIO9 "TEST POINT_TH" TP_0.7mm 3.75,50.343 r0 top
ISOH "USB 2.0 Type A Receptacle_for BMS" USB_2_0_Type_A_Receptacle_modify 7.685,78.969 r270 top value=61400416021
ISOHm "TEST POINT_TH" TP_0.7mm 16.811,73.289 r90 top
ISOHp "TEST POINT_TH" TP_0.7mm 16.811,84.593 r90 top
ISOLm "TEST POINT_TH" TP_0.7mm 51.322,72.578 r90 top
ISOLp "TEST POINT_TH" TP_0.7mm 51.322,64.515 r90 top
JP1 "Header 3x1" SIL_3x1 6.348,12.549 r90 top
M1 "Hole 3mm" M3 71.659,3.905 r0 top value=M3
M2 "Hole 3mm" M3 71.659,90.979 r0 top value=M3
M3 "Hole 3mm" M3 3.95,90.979 r0 top value=M3
M4 "Hole 3mm" M3 3.95,3.905 r0 top value=M3
P1 "Con 30p_2.00" "Con 30p_2.00" 37.924,2.353 r0 top
P2 "GND_BMS" SIL_2x1 3.911,61.56 r90 top value=61300211121
P3 "GND_EXT" SIL_2x1 72.472,12.609 r90 top value=61300211121
Q1 "STL8N10LF3" "PowerFLAT 5x6_WF type C" 57.493,55.106 r270 top
Q2 "STD105N10F7AG" DPAK_TO-252 18.117,1.642 r90 top
Q3 "BSS138" SOT-23 32.451,91.856 r90 bottom value=BSS138Q
Q4 "BSS138" SOT-23 29.187,91.856 r90 bottom value=BSS138Q
Q5 "BSS138" SOT-23 25.934,91.856 r90 bottom value=BSS138Q
Q6 "BSS138" SOT-23 22.676,91.856 r90 bottom value=BSS138Q
R1 "Resistor_1206" 1206R 69.582,38.772 r180 top value=10k
R2 "Resistor_0805" 0805R 57.18,10.106 r270 top value=N.M.
R3 "Res 10" 0603R 15.131,18.578 r90 top value=10
R4 "Resistor_0805" 0603R 58.081,22.02 r90 top value=100
R5 "Resistor_0603" 0603R 22.003,58.294 r270 top value=2.7k
R6 "Resistor_2010" 2010R 65.126,22.429 r90 bottom value=39
R7 "Res 10" 0603R 16.856,18.578 r90 top value=10
R8 "Resistor_0805" 0603R 55.351,22.02 r90 top value=100
R9 "Resistor_2010" 2010R 60.892,22.429 r90 bottom value=39
R10 "0R" 0603R 27.387,47.888 r180 top value=N.M.
R11 "Resistor_0805" 0603R 52.62,22.02 r90 top value=100
R12 "Resistor_2010" 2010R 56.658,22.429 r90 bottom value=39
R13 "0R" 0603R 27.387,52.146 r180 top value=N.M.
R14 "Resistor_0805" 0603R 49.89,22.02 r90 top value=100
R15 "Resistor_0603" 0603R 35.131,79.525 r90 bottom value=60.4
R16 "Resistor_2010" 2010R 52.424,22.429 r90 bottom value=39
R17 "Resistor_0805" 0603R 47.159,22.02 r90 top value=100
R18 "Resistor_0603" 0603R 35.147,76.77 r90 bottom value=60.4
R19 "Resistor_2010" 2010R 48.191,22.429 r90 bottom value=39
R20 "Resistor_0603" 0603R 29.163,51.567 r180 bottom value=10K
R21 "Resistor_0805" 0603R 44.429,22.02 r90 top value=100
R22 "Resistor_2010" 2010R 43.957,22.429 r90 bottom value=39
R23 "Resistor_0805" 0603R 41.698,22.02 r90 top value=100
R24 "Resistor_2010" 2010R 39.723,22.429 r90 bottom value=39
R25 "Resistor_0603" 0603R 40.612,68.002 r270 bottom value=60.4
R26 "Resistor_0805" 0603R 38.968,22.02 r90 top value=100
R27 "Resistor_0603" 0603R 40.604,70.789 r270 bottom value=60.4
R28 "Resistor_2010" 2010R 35.489,22.429 r90 bottom value=39
R29 "Resistor_0805" 0603R 36.237,22.02 r90 top value=100
R30 "Resistor_0805" 0805R 24.21,62.868 r90 bottom value=6.2K
R31 "Resistor_2010" 2010R 31.255,22.429 r90 bottom value=39
R32 "Resistor_0603" 0603R 26.242,64.318 r270 bottom value=18K
R33 "Resistor_0805" 0603R 33.507,22.02 r90 top value=100
R34 "Resistor_0805" 0805R 46.844,61.088 r270 top value=10k
R35 "Thermistor NTC_0603" 0603R 45.07,58.925 r90 top value=10k
R36 "Resistor_0603" 0603R 63.557,81.88 r180 top value=60.4
R37 "Resistor_0603" 0603R 43.549,58.925 r90 top value=3.9k
R38 "Resistor_2010" 2010R 27.021,22.429 r90 bottom value=39
R39 "Resistor_0603" 0603R 36.373,58.172 r90 bottom value=10K
R40 "Resistor_0805" 0603R 30.776,22.02 r90 top value=100
R41 "Resistor_2010" 2010R 22.788,22.429 r90 bottom value=39
R42 "Resistor_0603" 0603R 60.77,81.889 r180 top value=60.4
R43 "Resistor_0603" 0603R 33.721,58.172 r90 bottom value=10K
R44 "Resistor_0805" 0603R 28.046,22.02 r90 top value=100
R45 "Resistor_0805" 0805R 5.644,49.073 r0 bottom value=10k
R46 "Resistor_0805" 0805R 5.644,45.517 r0 bottom value=10k
R47 "Resistor_0805" 0805R 5.644,41.961 r0 bottom value=10k
R48 "Resistor_0805" 0805R 5.644,38.405 r0 bottom value=10k
R49 "Resistor_0805" 0805R 5.644,34.849 r0 bottom value=10k
R50 "Resistor_2010" 2010R 18.554,22.429 r90 bottom value=39
R51 "Resistor_0805" 0603R 25.3,22.02 r90 top value=100
R52 "Resistor_2010" 2010R 14.32,22.429 r90 bottom value=39
R53 "Resistor_2010" 2010R 10.403,50.343 r180 top value=1.5K
R54 "Resistor_2010" 2010R 10.403,46.533 r180 top value=1.5K
R55 "Resistor_2010" 2010R 10.403,42.723 r180 top value=1.5K
R56 "Resistor_0805" 0603R 22.569,22.02 r90 top value=100
R57 "Resistor_2010" 2010R 10.403,38.913 r180 top value=1.5K
R58 "Resistor_2010" 2010R 10.403,35.103 r180 top value=1.5K
R59 "Resistor_2010" 2010R 10.086,22.429 r90 bottom value=39
R60 "Resistor_0805" 0603R 19.82,22.02 r90 top value=100
R61 "N.M." 2512R 25.52,12.372 r0 bottom
R62 "Resistor_0603" 0603R 66.148,88.785 r180 top value=10K
R63 "Resistor_0603" 0603R 53.128,87.763 r180 top value=10K
R64 "Resistor_0603" 0603R 51.527,86.153 r0 top value=0
R65 "Resistor_0603" 0603R 51.527,90.981 r0 top value=10K
R66 "Resistor_0603" 0603R 51.527,89.372 r0 top value=10K
R67 "Resistor_0805" 0805R 47.956,81.746 r180 bottom value=6.2K
R68 "Resistor_0603" 0603R 34.697,64.561 r270 bottom value=750
R69 "Resistor_0805" 0603R 70.259,65.208 r180 bottom value=100
R70 "Resistor_0805" 0603R 70.259,67.748 r180 bottom value=100
R71 "Resistor_0603" 0603R 70.259,63.637 r180 bottom value=10K
R72 "Resistor_0805" 0603R 70.259,70.288 r180 bottom value=100
R73 "Resistor_0805" 0603R 70.259,72.828 r180 bottom value=100
R74 "Resistor_0603" 0603R 30.7,93.595 r0 top value=1.1k
R75 "Resistor_0805" 0603R 47.615,89.631 r270 bottom value=100
R76 "Resistor_0805" 0603R 45.075,89.631 r270 bottom value=100
R77 "Resistor_0603" 0603R 27.457,93.595 r0 top value=1.1k
R78 "Resistor_0603" 0603R 24.193,93.605 r0 top value=1.1k
R79 "Resistor_0603" 0603R 20.926,93.595 r0 top value=750
R80 "Resistor_0805" 0603R 42.535,89.631 r270 bottom value=100
R81 "Resistor_0603" 0603R 30.7,90.168 r0 bottom value=110K
R82 "Resistor_0805" 0603R 39.995,89.631 r270 bottom value=100
R83 "Resistor_0805" 0603R 37.455,89.631 r270 bottom value=100
R84 "Resistor_0805" 0603R 34.915,89.631 r270 bottom value=100
R85 "Resistor_0603" 0603R 27.457,90.168 r0 bottom value=10K
R86 "Resistor_0603" 0603R 24.183,90.168 r0 bottom value=10K
R87 "Resistor_0603" 0603R 20.925,90.168 r0 bottom value=10K
R88 "if using a single voltage" 0805R 70.107,78.796 r90 bottom value=N.M.
R89 "Resistor_0603" 0603R 62.408,75.807 r0 bottom value=750
RG "Resistor_0603" 0603R 10.196,14.478 r180 top value=1K
RHOT "Resistor_2512" 2512R 10.277,9.895 r0 top value=47
RMREG "100K" 0603R 55.442,51.26 r90 top value=N.M.
RPD "Resistor_0603" 0603R 10.196,17.52 r180 top value=100K
S1 "TEST POINT_TH" TP_0.7mm 10.086,29.028 r0 top
S2 "TEST POINT_TH" TP_0.7mm 14.32,29.028 r0 top
S3 "TEST POINT_TH" TP_0.7mm 18.554,29.028 r0 top
S4 "TEST POINT_TH" TP_0.7mm 22.788,29.028 r0 top
S5 "TEST POINT_TH" TP_0.7mm 27.021,29.028 r0 top
S6 "TEST POINT_TH" TP_0.7mm 31.299,29.028 r0 top
S7 "TEST POINT_TH" TP_0.7mm 35.489,29.028 r0 top
S8 "TEST POINT_TH" TP_0.7mm 39.823,29.028 r0 top
S9 "TEST POINT_TH" TP_0.7mm 43.957,29.028 r0 top
S10 "TEST POINT_TH" TP_0.7mm 48.191,29.028 r90 top
S11 "TEST POINT_TH" TP_0.7mm 52.424,29.028 r0 top
S12 "TEST POINT_TH" TP_0.7mm 56.658,29.028 r90 top
S13 "TEST POINT_TH" TP_0.7mm 60.892,29.028 r90 top
S14 "TEST POINT_TH" TP_0.7mm 65.126,29.028 r90 top
T1 "ESMIT-4180/A" ESMIT4180 25.501,80.202 r180 bottom value=120uH
T2 "ESMIT-4180/A" ESMIT4180 59.821,67.293 r180 top value=120uH
text1 "Label_China RoHS" "LOGO CHINA ROHS 10" 53.622,50.825 r180 bottom
text2 "Label_RoHS" "LOGO RoHS - 3" 64.254,41.646 r180 bottom
text3 "Label_SERIAL NUMBER" "LOGO SERIAL NUMBER" 153.833,20.863 r90 bottom
text4 "Label_Weee symbol" "LOGO CESTINO" 53.18,43.425 r180 bottom
text7 "Label_CE" "LOGO CE" 64.742,50.794 r180 bottom
text9 "Label_FOR EVALUATION ..." "LOGO FOR EVALUATION ..." 88.608,18.932 r90 bottom
TP1 "TEST POINT_TH" TP_0.7mm 57.137,57.55 r0 top
TP2 "TEST POINT" TP_0.9mm 59.007,64.515 r180 top
TP3 "TEST POINT" TP_0.9mm 59.007,72.578 r90 top
TP4 "SDO" TP_0.9mm 66.764,65.208 r270 top
TP5 "SCK" TP_0.9mm 66.764,67.748 r270 top
TP6 "SDI" TP_0.9mm 66.764,70.288 r270 top
TP7 "NCS" TP_0.9mm 66.764,72.828 r270 top
TP8 "FAULT" TP_0.9mm 47.615,86.036 r0 top
TP9 "DIS" TP_0.9mm 45.075,86.036 r0 top
TP10 "ISOFreq" TP_0.9mm 42.535,86.036 r0 top
TP11 "BNE" TP_0.9mm 39.995,86.036 r0 top
TP12 "TXEN" TP_0.9mm 37.455,86.036 r0 top
TP13 "TXAmp" TP_0.9mm 34.915,86.036 r0 top
TP14 "GND" TP_0.9mm 53.252,80.021 r90 top
TP15 "GND" TP_0.9mm 73.604,86.997 r90 top
U1 "L9963E" TQFP64 37.691,49.536 r270 top
U2 "USBLC6-2SC6Y" SOT23-6L 30.096,79.919 r270 bottom
U3 "USBLC6-2SC6Y" SOT23-6L 45.555,67.649 r90 bottom
U4 "L9963T" SO16N 63.272,91.41 r180 top
U5 "USBLC6-2SC6Y" SOT23-6L 62.293,77.098 r180 top
U6 "DC, 35V, 60mA" WL-OCPT_SOP4 46.93,76.527 r90 top value=140357145300
VANA "TEST POINT_TH" TP_0.7mm 18.805,53.461 r90 top
VBATT "TEST POINT_TH" TP_0.7mm 59.484,38.253 r90 top
VCOM "TEST POINT_TH" TP_0.7mm 40.808,60.466 r90 top
VREG "TEST POINT_TH" TP_0.7mm 24.144,55.491 r90 top
VTREF "TEST POINT_TH" TP_0.7mm 24.144,53.461 r90 top

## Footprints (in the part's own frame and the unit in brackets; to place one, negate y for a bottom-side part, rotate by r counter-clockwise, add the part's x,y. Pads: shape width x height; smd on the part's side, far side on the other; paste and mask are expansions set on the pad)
0603C [mm]
  rect 0.6x1 smd: 1(0,0) 2(1.593,0)
  silkscreen extent -0.47,-0.66 2.07,0.66, body extent -0.04,-0.46 1.66,0.44, height 0.9
0603R [mm]
  rect 0.6x1 smd: 1(0,0) 2(1.593,0)
  silkscreen extent -0.47,-0.66 2.07,0.66, body extent -0.25,-0.39 1.85,0.41, height 0.51
0805C [mm]
  rect 0.8x1.4 smd: 1(0,0) 2(2.013,0)
  silkscreen extent -0.59,-0.89 2.61,0.89, body extent -0.07,-0.67 2.03,0.67, height 0.95
0805L [mm]
  rect 0.8x1.4 smd: 1(0,0) 2(2.013,0)
  silkscreen extent -0.59,-0.89 2.61,0.89, body extent -0.12,-0.72 2.08,0.72, height 1.05
0805R [mm]
  rect 0.8x1.4 smd: 1(0,0) 2(2.013,0)
  silkscreen extent -0.59,-0.89 2.61,0.89, body extent -0.25,-0.63 2.27,0.63, height 0.51
1206C [mm]
  rect 1.048x1.85 smd: 1(0,0) 2(3.226,0)
  silkscreen extent -0.76,-1.14 3.99,1.14, body extent -0.07,-0.87 3.28,0.87, height 1.4
1206R [mm]
  rect 1.048x1.85 smd: 1(0,0) 2(3.226,0)
  silkscreen extent -0.76,-1.14 3.99,1.14, body extent -0.29,-0.81 3.51,0.79, height 0.61
1210C [mm]
  rect 1x3 smd: 1(0,0) 2(3.099,0)
  silkscreen extent -0.74,-1.75 3.84,1.75, body extent -0.2,-1.35 3.3,1.35, height 1.8
2010R [mm]
  rect 1.2x3 smd: 1(0,0) 2(4.7,0)
  silkscreen extent -0.82,-1.75 5.53,1.75, body extent -0.15,-1.25 4.85,1.25, height 0.61
2512R [mm]
  rect 1.4x3.5 smd: 1(0,0) 2(6.426,0)
  silkscreen extent -0.91,-1.98 7.34,1.98, body extent -0.17,-1.55 6.63,1.55, height 0.61
"Con 30p_2.00" [mm] "2.00mm Male Dual Row Horizontal Shrouded Header with positive locking, 30p"
  rect 1.3x1.3 hole 0.8: 1(14,2.45)
  round 1.3 hole 0.8: 2(14,4.95) 3(12,2.45) 4(12,4.95) 5(10,2.45) 6(10,4.95) 7(8,2.45) 8(8,4.95) 9(6,2.45) 10(6,4.95) 11(4,2.45) 12(4,4.95) 13(2,2.45) 14(2,4.95) 15(0,2.45) 16(0,4.95) 17(-2,2.45) 18(-2,4.95) 19(-4,2.45) 20(-4,4.95) 21(-6,2.45) 22(-6,4.95) 23(-8,2.45) 24(-8,4.95) 25(-10,2.45) 26(-10,4.95) 27(-12,2.45) 28(-12,4.95) 29(-14,2.45) 30(-14,4.95)
  silkscreen extent -16.85,-8 16.85,7.4, body extent -16.7,-7.25 16.7,7.25, height 11.73
DPAK_TO-252 [mm]
  rect 1.5x2.9 smd paste+0 mask+0: 1(0,0) 3(4.57,0)
  rect 6.604x6.9 smd paste+0 mask+0: 2(2.285,6.808)
  silkscreen extent -1.14,1.65 5.71,10.41, body extent -1.02,0.58 5.59,9.35, height 2.42
ESMIT4180 [mil]
  rect 55x55 smd: 1(0,0) 2(0,-100) 3(360,-100) 4(360,0)
  silkscreen extent 7,-152 321,60, body extent -5,-152 364,53, height 142
KK254_4p [mm]
  rrect30% 1.5x1.5 hole 1: 1(0,0)
  round 1.5 hole 1: 2(-2.54,0) 3(-5.08,0) 4(-7.62,0)
  silkscreen extent -9.07,-3.3 2.16,2.7, body extent -8.89,-3.2 1.27,2.6, height 11.51
KK254_6P [mm]
  rrect30% 1.5x1.5 hole 1: 1(0,0)
  round 1.5 hole 1: 2(-2.54,0) 3(-5.08,0) 4(-7.62,0) 5(-10.16,0) 6(-12.7,0)
  silkscreen extent -14.14,-3.38 2.18,2.72, body extent -13.97,-3.2 1.27,2.6, height 11.51
LED_0805 [mm]
  rect 0.7x1.4 smd: 1(0,0) 2(-1.813,0)
  silkscreen extent -2.36,-0.89 0.56,0.89, body extent -1.88,-0.62 0.12,0.63, height 0.7
"LOGO CE" [mm]
  silkscreen extent -3.69,-2.62 3.97,2.85
"LOGO CESTINO" [mm]
  silkscreen extent -2.2,-3.95 2.29,2.41
"LOGO CHINA ROHS 10" [mm]
  silkscreen extent -3.34,-3.1 3.54,2.87
"LOGO FOR EVALUATION ..." [mm]
"LOGO RoHS - 3" [mm]
  silkscreen extent -4,-2 4,3
"LOGO SERIAL NUMBER" [mm]
M3 [mm]
  round 4.5 hole 3.2: 1(0.008,0)
  silkscreen extent -2.98,-2.98 2.98,2.98, body extent -3,-3 3,3, height 2.48
"PowerFLAT 5x6_WF type C" [mm]
  rect 0.65x1.25 smd: 1(0,0) 2(1.27,0) 3(2.54,0) 4(3.81,0)
  rect 0.72x0.9 smd: 5(3.845,5.87) 6(2.545,5.865) 7(1.268,5.86) 8(-0.032,5.868)
  Top Layer region: -0.392,1.52 4.208,1.52 4.208,5.43 -0.392,5.43
  Top Layer region: 4.093,4.166 4.693,4.166 4.693,5.066 4.093,5.066
  Top Layer region: -0.887,4.162 -0.287,4.162 -0.287,5.062 -0.887,5.062
  Top Layer region: 4.091,1.713 4.691,1.713 4.691,2.613 4.091,2.613
  Top Layer region: -0.887,1.713 -0.287,1.713 -0.287,2.613 -0.887,2.613
  silkscreen extent -1.29,-0.31 4.49,5.84, body extent -0.71,-0.31 4.49,5.84, height 0.95
SIL_2x1 [mm] "Pin Header, pitch 2.54 mm, THT, Vertical, single row, 4p"
  rrect30% 2x2 hole 1.3: 1(0,0)
  round 2 hole 1.3: 2(2.54,0)
  silkscreen extent -1.45,-1.45 4.04,1.45, body extent -1.24,-1.3 3.84,1.24, height 8.55
SIL_3x1 [mm] "Pin Header, pitch 2.54 mm, THT, Vertical, single row, 4p"
  rrect30% 2x2 hole 1.3: 1(0,0)
  round 2 hole 1.3: 2(2.616,-0.025) 3(5.08,0)
  silkscreen extent -1.37,-1.42 6.63,1.42, body extent -1.19,-1.3 6.43,1.24, height 8.55
SMA [mm]
  rect 1.4x1.64 smd mask+0.05: 1(0,0) 2(-4.025,0)
  silkscreen extent -4.57,-1.5 0.53,1.43, body extent -4.44,-1.35 0.4,1.35, height 2.08
SO16N [mm]
  rect 0.65x1.75 smd: 1(0,0) 2(1.27,0) 3(2.54,0) 4(3.81,0) 5(5.08,0) 6(6.35,0) 7(7.62,0) 8(8.89,0) 9(8.89,5.85) 10(7.62,5.85) 11(6.35,5.85) 12(5.08,5.85) 13(3.81,5.85) 14(2.54,5.85) 15(1.27,5.85) 16(0,5.85)
  silkscreen extent -0.55,0.93 9.45,4.93, body extent -0.54,-0.11 9.46,6, height 1.75
SOD-323 [mm]
  rect 0.8x0.57 smd mask+0.05: 1(0,0) 2(-2.456,0)
  silkscreen extent -2.2,-0.86 -0.25,0.91, body extent -2.59,-0.6 0.13,0.65, height 1.05
SOT23-6L [mm]
  rect 0.7x1.3 smd mask+0.05: 1(0,0) 2(0.95,0) 3(1.9,0) 4(1.9,2.7) 5(0.95,2.7) 6(0,2.7)
  silkscreen extent -0.95,-0.08 2.45,2.23, body extent -0.6,-0.15 2.45,2.85, height 1.4
SOT-23 [mm]
  rect 1.5x0.6 smd: 1(0,0) 2(0,-1.9) 3(1.5,-0.95)
  silkscreen extent 0.1,-2.4 1.4,0.5, body extent -0.49,-2.44 2.01,0.56, height 1.09
TP_0.7mm [mm]
  round 1.4 hole 0.7: 1(0,0)
  silkscreen extent -0.8,-0.8 0.8,0.8
TP_0.9mm [mm]
  round 1.4 hole 0.9: 1(0,0)
  silkscreen extent -0.8,-0.8 0.8,0.8
TQFP64 [mm] "TQFP64 Exp, 64-Leads, Body 10x10mm (max), Pitch 0.50mm, IPC Medium Density"
  rect 1.75x0.3 smd mask+0.05: 1(-5.575,3.75)
  oval 1.75x0.3 smd mask+0.05: 2(-5.575,3.25) 3(-5.575,2.75) 4(-5.575,2.25) 5(-5.575,1.75) 6(-5.575,1.25) 7(-5.575,0.75) 8(-5.575,0.25) 9(-5.575,-0.25) 10(-5.575,-0.75) 11(-5.575,-1.25) 12(-5.575,-1.75) 13(-5.575,-2.25) 14(-5.575,-2.75) 15(-5.575,-3.25) 16(-5.575,-3.75) 33(5.575,-3.75) 34(5.575,-3.25) 35(5.575,-2.75) 36(5.575,-2.25) 37(5.575,-1.75) 38(5.575,-1.25) 39(5.575,-0.75) 40(5.575,-0.25) 41(5.575,0.25) 42(5.575,0.75) 43(5.575,1.25) 44(5.575,1.75) 45(5.575,2.25) 46(5.575,2.75) 47(5.575,3.25) 48(5.575,3.75)
  oval 0.3x1.75 smd mask+0.05: 17(-3.75,-5.575) 18(-3.25,-5.575) 19(-2.75,-5.575) 20(-2.25,-5.575) 21(-1.75,-5.575) 22(-1.25,-5.575) 23(-0.75,-5.575) 24(-0.25,-5.575) 25(0.25,-5.575) 26(0.75,-5.575) 27(1.25,-5.575) 28(1.75,-5.575) 29(2.25,-5.575) 30(2.75,-5.575) 31(3.25,-5.575) 32(3.75,-5.575) 49(3.75,5.575) 50(3.25,5.575) 51(2.75,5.575) 52(2.25,5.575) 53(1.75,5.575) 54(1.25,5.575) 55(0.75,5.575) 56(0.25,5.575) 57(-0.25,5.575) 58(-0.75,5.575) 59(-1.25,5.575) 60(-1.75,5.575) 61(-2.25,5.575) 62(-2.75,5.575) 63(-3.25,5.575) 64(-3.75,5.575)
  rect 1x1 smd: 65(-3,3) 65(-3,1.5) 65(-3,0) 65(-3,-1.5) 65(-3,-3) 65(-1.5,3) 65(-1.5,1.5) 65(-1.5,0) 65(-1.5,-1.5) 65(-1.5,-3) 65(0,3) 65(0,1.5) 65(0,0) 65(0,-1.5) 65(0,-3) 65(1.5,3) 65(1.5,1.5) 65(1.5,0) 65(1.5,-1.5) 65(1.5,-3) 65(3,3) 65(3,1.5) 65(3,0) 65(3,-1.5) 65(3,-3)
  silkscreen extent -5.7,-4.3 4.3,4.58, body extent -5,-5 5,5, height 1.6
USB_2_0_Type_A_Receptacle_modify [mm] "USB 2.0 Type A Horizontal"
  round 1.42 hole 0.92: 1(3.5,5.99) 2(1,5.99) 3(-1,5.99) 4(-3.5,5.99)
  round 3.45 hole 2.3: SHELL(-6.57,3.28) SHELL(6.57,3.28)
  silkscreen extent -7.25,-7 7.25,7, body extent -8,-7 8,7, height 7.63
WL-OCPT_SOP4 [mm] "Optocoupler Phototransistor, body 4.4x3.6mm"
  rrect50% 1.1x0.9 smd: 1(-3.15,1.27) 2(-3.15,-1.27) 3(3.15,-1.27) 4(3.15,1.27)
  silkscreen extent -3.27,-1.9 2.3,2.37, body extent -3.5,-1.8 3.5,1.8, height 2.1

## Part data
B2_1 B4_3 B6_5 B8_7 B10_9 B12_11 B14_13 CELL0 CELL1 CELL2 CELL3 CELL4 CELL5 CELL6 CELL7 CELL8 CELL9 CELL10 CELL11 CELL12 CELL13 CELL14 GND GPIO1 GPIO2 GPIO3 GPIO4 GPIO5 GPIO6 GPIO8 GPIO9 ISOHm ISOHp ISOLm ISOLp S1 S2 S3 S4 S5 S6 S7 S8 S9 S10 S11 S12 S13 S14 TP1 VANA VBATT VCOM VREG VTREF: "Test point_hole"
C1 C8 C15 C19 C21 C29 C31 C33 C40 C42 C45 C48 C50 C57 C59 C71 C75 C76: library part "Cap 47nF", "0603 - 50V - X7R Class II", Manufacturer=WE, Part Number=885012206093, Voltage=50V
C2: library part "Cap 4.7uF", "1206 - 50V - X7R Class II", Manufacturer=WE, Part Number=885012208094, Voltage=50V
C3: library part "Cap 2.2uF_1210", "1210 - 100V - X7R Class II", Manufacturer=WE, Part Number=885012209071, Voltage=100V
C4 C6 C14: library part "Cap 100nF_0603", "0603 - 100V - X7R Class II", Manufacturer=WE, Part Number=885012206120, Voltage=100V
C5: library part "Cap 100pF_0603", "0603 - 100V - X7R Class II", Manufacturer=WE, Part Number=885012206102, Voltage=100V
C7 C12: library part "Cap N.M._0603", "0603 - xxV -  xxxx"
C9 C17 C20 C23 C30 C32 C35 C41 C43 C46 C49 C51 C58 C60: library part "Cap 10nF_(bms)", "0603 - 50V -  X7R Class II", Manufacturer=WE, Part Number=885012206089, Voltage=50V
C10: library part "Cap 220nF", "0603 - 50V - X7R Class II", Manufacturer=WE, Part Number=885012206125, Voltage=50V
C11 C13: library part "Cap 2.2uF", "0805 - 25V -  X7R Class II", Manufacturer=WE, Part Number=885012207079, Voltage=25V
C16 C82: "0603 - 50V - NP0 Class I", Manufacturer=WE, Part Number=885012006053, Voltage=50V
C18 C25 C37: library part "Cap 1uF_0805", "0805 - 50V -  X7R Class II", Manufacturer=WE, Part Number=885012207103, Voltage=50V
C22 C26 C34 C39: library part "Cap 22pF", "0603 - 50V - NP0 Class I", Manufacturer=WE, Part Number=885012006053, Voltage=50V
C24 C36: library part "Cap 10nF", "0603 - 50V -  X7R Class II", Manufacturer=WE, Part Number=885012206089, Voltage=50V
C27 C28 C38 C81: library part "Cap N.M._1206", "1206 - xxV -  xxxx"
C44 C61 C62 C63 C64 C65: library part "Cap 2.2nF", "0603 - 50V - X7R Class II", Manufacturer=WE, Part Number=885012206085, Voltage=50V
C47 C66 C67 C68 C69 C70: library part "Cap 6.8nF", "0603 - 50V - X7R Class II", Manufacturer=WE, Part Number=885012206088, Voltage=50V
C52 C53 C54 C55 C56 C77 C78: library part "Cap 100nF", "0603 - 50V - X7R Class II", Manufacturer=WE, Part Number=885012206095, Voltage=50V
C72: library part "Cap 10uF", "1210 - 50V - X7R Class II", Manufacturer=WE, Part Number=885012209073, Voltage=50V
C73: library part "Cap 68nF", "0603 - 50V - X7R Class II", Manufacturer=WE, Part Number=885012206094, Voltage=50V
C74: library part "Cap 33pF", "0603 - 50V - NP0 Class I", Manufacturer=WE, Part Number=885012006054, Voltage=50V
C79: "0603 - 50V -  X7R Class II", Manufacturer=WE, Part Number=885012206089, Voltage=50V
C80 C83 C84: "0805 - 50V -  X7R Class II", Manufacturer=WE, Part Number=885012207103, Voltage=50V
CGS: library part "Cap 4.7nF", "0603 - 50V - X7R Class II", Manufacturer=WE, Part Number=885012206087, Voltage=50V
CN1 CN3: "2.54mm - 1 row - KK254 - Male", Current=3A, Manufacturer=WE, Part Number=61900411121, Voltage=250VAC
CN2: "2.54mm - 1 row - KK254 - Male", Current=3A, Manufacturer=WE, Part Number=61900611121, Voltage=250VAC
D1 D4: "Automotive 600 W, 68V TVS in SMA", Manufacturer=STMicroelectronics, Power=600W, Voltage=68V
D2 D9: "0805 - Led Green - 3.2V", Manufacturer=WE, Part Number=150080GS75000, Voltage=3.2V
D3: "4.7V Zener Voltage Regulators, 300mW", Manufacturer=Onsemi, Power=300mW, Voltage=4.7V
D5: "0805 - Led Red - 2V", Manufacturer=WE, Part Number=150080RS75000, Voltage=2V
D6: "0805 - Led Amber - 2V", Manufacturer=WE, Part Number=150080AS75000, Voltage=2V
D7: "0805 - Led Yellow - 2V", Manufacturer=WE, Part Number=150080YS75000, Voltage=2V
D8: "0805 - Led Blue - 3.2V", Manufacturer=WE, Part Number=150080BS75000, Voltage=3.2V
FB1 FB2 FB3 FB4 FB5 FB6 FB7 FB8 FB9 FB10 FB11 FB12 FB13 FB14 FB15 FB16: library part "Ferrite Bead 1K_0805", "Ferrite Beads Multi-Layer Power 1KOhm 25% 100MHz 1.5A 0.15Ohm DCR 0805", Current=1.5A, Manufacturer=TDK
ISOH: library part "USB 2.0 Type A Receptacle", "USB 2.0 Type A, Receptacle, Horizontal, THT", Current=1.5A, Manufacturer=WE, Part Number=61400416021, Voltage=30V
JP1: library part "Jumper 3p", "THT Vertical 3 pins Header, Pitch 2.54 mm, Single Row", Current=3A, Manufacturer=WE, Part Number=61300311121, Voltage=250VAC
M1 M2 M3 M4: library part Screw_3mm, "WA-SCRW Pan Head Screw w. cross slot M3", Manufacturer=WE, Part Number=97790403111
P1: "2.00mm - WR-WTB - Male Dual Row Horizontal Shrouded Header w. positive locking", Current=3A, Manufacturer=WE, Part Number=62403021722, Voltage="250V AC"
P2 P3: library part "Header 2p 2.54", "2.54mm - WR-PHD Pin Header, THT, pitch 2.54mm, Single Row, Vertical, 2p", Current=3A, Manufacturer=WE, Part Number=61300211121, Voltage="250V (AC)"
Q1: "Automotive-grade N-channel 100 V, 25 mΩ typ., 7.8 A STripFET™ F3 Power MOSFET in a PowerFLAT™ 5x6 package", Current=7.8A, Manufacturer=STMicroelectronics, Power=70W, Voltage=100V
Q2: "Automotive-grade N-channel 100 V, 6.8 mΩ typ., 80 A, / STripFET™ F7 Power MOSFET in a DPAK package", Current=80A, Manufacturer=STMicroelectronics, Power=120W, Voltage=100V
Q3 Q4 Q5 Q6: "N-Channel Enhancement Mosfet", Current=0.2A, Manufacturer=NEXPERIA, Part Number=BSS138Q-7-F, Power=0.3W, Voltage=50
R1: library part "Res 10K_1206", "1206 - ±1%  -  0.66W", Manufacturer=Panasonic, Part Number=ERJUP8F1002V, Power=0.66W
R2: library part "Res N.M._0805", "0805 - xx% - xxxx"
R3 R7: "0603 - ±1%  -  0.25W", Manufacturer=Panasonic, Part Number=ERJPA3F10R0V
R4 R8 R11 R14 R17 R21 R23 R26 R29 R33 R40 R44 R51 R56 R60: library part "Res 100", "0603 - ±1%  -  0.25W", Manufacturer=Panasonic, Part Number=ERJPA3F1000V, Power=0.25W
R5: library part "Res 2.7k", "0603 - ±1%  -  0.125W", Manufacturer=Vishay, Part Number=MCT06030C2701FP500, Power=0.125W
R6 R9 R12 R16 R19 R22 R24 R28 R31 R38 R41 R50 R52 R59: library part "Res 39_2010", "2010 - ±1%  -  1.25W", Manufacturer="TE Connectivity", Part Number=CRGP2010F39R, Power=1.25W
R10 R13 RMREG: library part "Res N.M._0603", "0603 - xx% - xxxx"
R15 R18 R25 R27 R36 R42: library part "Res 60.4", "0603 - ±1%  -  0.1W", Manufacturer=Panasonic, Part Number=ERJ3EKF60R4V, Power=0.1W
R20 R39 R43: library part "Res 10K", "0603 - ±1%  -  0.2W", Manufacturer=Panasonic, Part Number=ERJP03F1002V, Power=0.2W
R30 R67: library part "Res 6.2K_0805", "0805 - ±1%  -  0.5W", Manufacturer=Panasonic, Part Number=ERJP06F6201V, Power=0.55W
R32: library part "Res 18K", "0603 - ±1%  -  0.2W", Manufacturer=Panasonic, Part Number=ERJP03F1802V, Power=0.2W
R34 R45 R46 R47 R48 R49: library part "Res 10K_0805", "0805 - ±1%  -  0.5W", Manufacturer=Panasonic, Part Number=ERJP6WF1002V, Power=0.5W
R35: library part "NTC 10k_0603", "0603 - ±1%  -  0.1W", Manufacturer=TDK, Part Number=NTCG163JH103HTDS
R37: library part "Res 3.9k", "0603 - ±1%  -  0.1W", Manufacturer=Panasonic, Part Number=ERJ3EKF3901V, Power=0.1W
R53 R54 R55 R57 R58: library part "Res 1.5K_2010", "2010 - ±1%  -  2W", Manufacturer="TE Connectivity", Part Number=35021K5FT, Power=2W
R61: library part "Res N.M.", "xxxx- ±xx%  -  xxxx"
R62 R63 R65 R66 R71 R85 R86 R87: library part "Res 10K", "0603 - ±1%  -  0.2W", Manufacturer=Panasonic, Part Number=ERJP03F1002V, Power="1/4 W"
R64: library part "Res 0", "0603 - ±1% - 0.1W", Manufacturer=Panasonic, Part Number=ERJ3GEY0R00V, Power=0.1W
R68: library part "Res 750", "0603 - ±0.5%  -  0.25W", Manufacturer=Panasonic, Part Number=ERJUP3D7500V, Power=0.25W
R69 R70 R72 R73 R75 R76 R80 R82 R83 R84: library part "Res 100", "0603 - ±1%  -  0.25W", Manufacturer=Panasonic, Part Number=ERJPA3F1000V, Power="1/4 W"
R74 R77 R78: library part "Res 1.1k", "0603 - ±1%  -  0.25W", Manufacturer=Panasonic, Part Number=ERJPA3F1101V, Power=0.25W
R79 R89: library part "Res 750", "0603 - ±1%  -  0.25W", Manufacturer=Panasonic, Part Number=ERJUP3D7500V, Power=0.25W
R81: library part "Res 110K", "0603 - ±1%  -  0.25W", Manufacturer=Panasonic, Part Number=ERJPA3F1103V, Power=0.25W
R88: library part "Res N.M.", "xxxx - xx% - xxxx"
RG: library part "Res 1K", "0603 - ±1%  -  0.25W", Manufacturer=Panasonic, Part Number=ERJPA3F1001V, Power=0.25W
RHOT: library part "Res 47_2512", "2512 - ±5%  -  1W", Manufacturer="TE Connectivity", Part Number=352047RJT, Power=1W
RPD: library part "Res 100K", "0603 - ±1%  -  0.25W", Manufacturer=Panasonic, Part Number=ERJP03F1003V
T1 T2: "Pulse Transformers 120uH", Manufacturer="Sumida America Inc."
TP2 TP3: "Test point"
TP4 TP5 TP6 TP7 TP8 TP9 TP10 TP11 TP12 TP13 TP14 TP15: library part "TEST POINT", "Test point"
U1: "Automotive chip for battery management applications with daisy chain up to 31 devices", Manufacturer=STMicroelectronics, Voltage="upto 64V"
U2 U3: "Automotive ESD protection for high speed interfaces.", Manufacturer=STMicroelectronics
U4: "Automotive general purpose SPI to isolated SPI transceiver", Manufacturer=STM, Voltage=5V
U5: "Automotive ESD protection for high speed interfaces.", Manufacturer=STM
U6: library part 140357145300, "WL-OCPT Optocoupler Phototransistor, SOP4, 1 Channel, DC, 35V, 60mA", Current=60mA, Manufacturer=WE, Voltage=35V

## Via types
v1: diameter 0.55, hole 0.3, Top Layer to Bottom Layer, tented both sides, 364 vias
v2: diameter 0.55, hole 0.3, Top Layer to Bottom Layer, 36 vias

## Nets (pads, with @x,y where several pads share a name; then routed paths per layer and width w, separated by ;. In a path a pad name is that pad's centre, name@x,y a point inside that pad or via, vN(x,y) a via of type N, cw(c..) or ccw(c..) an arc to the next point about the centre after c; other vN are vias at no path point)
BNE: Q5.1 R65.2 R82.2 R86.2 TP11.1 U4.8 | length 55.3
  Top Layer w0.3: R65.2@53.121,90.981 53.953,90.981 U4.8@54.382,91.41 54.382,90.15 v1(54.361,90.129)
  Layer 2 w0.3: v1(26.334,90.895) 26.975,90.253 31.261,90.253 34.264,93.256 53.836,93.256 54.361,92.731 v1(54.361,90.129) 54.361,89.526 54.004,89.169 43.128,89.169 TP11.1@39.995,86.036
  Bottom Layer w0.3: R86.2@25.777,90.168 25.934,90.325 Q5.1@25.934,91.856 ; TP11.1@39.995,86.036 R82.2@39.995,88.038
C0: C71.2 CELL0.1 FB16.1 P1.16 | length 29
  Top Layer w0.3: FB16.1@19.854,18.516 CELL0.1@19.854,16.921 19.854,13.393 23.403,9.844 37.642,9.844 37.924,9.562 P1.16@37.924,7.303
  Bottom Layer w0.3: P1.16@37.924,7.303 C71.2@37.924,9.303
C1: C59.2 CELL1.1 FB15.1 P1.15 | length 30.6
  Top Layer w0.3: FB15.1@22.585,18.516 CELL1.1@22.585,16.921 22.585,13.33 25.571,10.344 38.655,10.344 38.924,10.075 38.924,5.803 P1.15@37.924,4.803
  Bottom Layer w0.3: C59.2@37.924,2.803 P1.15@37.924,4.803
C2: C57.2 CELL2.1 FB14.1 P1.14 | length 26.3
  Top Layer w0.3: FB14.1@25.315,18.516 CELL2.1@25.315,16.921 25.315,13.35 27.784,10.881 39.748,10.881 39.924,10.705 P1.14@39.924,7.303
  Bottom Layer w0.3: P1.14@39.924,7.303 C57.2@39.924,9.303
C3: C50.2 CELL3.1 FB13.1 P1.13 | length 28
  Top Layer w0.2: FB13.1@27.975,18.4 FB13.1@28.091,18.516
  Top Layer w0.3: FB13.1@28.091,18.516 CELL3.1@28.091,16.921 28.091,13.362 28.968,12.485 39.961,12.485 40.924,11.522 40.924,5.803 P1.13@39.924,4.803
  Bottom Layer w0.3: C50.2@39.924,2.803 P1.13@39.924,4.803
C4: C48.2 CELL4.1 FB12.1 P1.12 | length 24.1
  Top Layer w0.3: FB12.1@30.776,18.516 CELL4.1@30.776,16.921 30.776,13.344 31.135,12.985 41.41,12.985 42.285,12.11 42.285,7.935 41.924,7.574 P1.12@41.924,7.303
  Bottom Layer w0.3: P1.12@41.924,7.303 C48.2@41.924,9.303
C5: C45.2 CELL5.1 FB11.1 P1.11 | length 24.7
  Top Layer w0.3: FB11.1@33.507,18.516 33.507,16.921 33.507,13.825 33.846,13.485 41.862,13.485 42.924,12.423 42.924,5.803 P1.11@41.924,4.803
  Bottom Layer w0.3: C45.2@41.924,2.803 P1.11@41.924,4.803
C6: C42.2 CELL6.1 FB10.1 P1.10 | length 20.1
  Top Layer w0.3: FB10.1@36.237,18.516 CELL6.1@36.237,16.921 36.237,14.295 36.547,13.985 42.849,13.985 43.547,13.287 43.547,7.951 43.924,7.574 P1.10@43.924,7.303
  Bottom Layer w0.3: P1.10@43.924,7.303 C42.2@43.924,9.303
C7: C40.2 CELL7.1 FB9.1 P1.9 | length 21.3
  Top Layer w0.3: FB9.1@38.968,18.516 CELL7.1@38.968,16.921 38.968,14.74 39.223,14.485 43.803,14.485 44.924,13.364 44.924,5.803 P1.9@43.924,4.803
  Bottom Layer w0.3: C40.2@43.924,2.803 P1.9@43.924,4.803
C8: C33.2 CELL8.1 FB8.1 P1.8 | length 16.7
  Top Layer w0.3: FB8.1@41.698,18.516 CELL8.1@41.698,16.921 41.698,15.161 41.874,14.985 44.794,14.985 45.609,14.17 45.609,8.032 45.733,7.909 45.733,7.494 P1.8@45.924,7.303
  Bottom Layer w0.3: P1.8@45.924,7.303 C33.2@45.924,9.303
C9: C31.2 CELL9.1 FB7.1 P1.7 | length 17.8
  Top Layer w0.3: FB7.1@44.429,18.516 CELL9.1@44.429,16.921 44.429,15.717 44.604,15.541 45.671,15.541 46.924,14.288 46.924,5.803 P1.7@45.924,4.803
  Bottom Layer w0.3: C31.2@45.924,2.803 P1.7@45.924,4.803
C10: C29.2 CELL10.1 FB6.1 P1.6 | length 13.9
  Top Layer w0.3: FB6.1@47.159,18.516 CELL10.1@47.159,16.921 47.159,15.521 48.325,14.355 48.325,7.974 47.924,7.574 P1.6@47.924,7.303
  Bottom Layer w0.3: P1.6@47.924,7.303 C29.2@47.924,9.303
C11: C21.2 CELL11.1 FB5.1 P1.5 | length 16.5
  Top Layer w0.3: P1.5@47.924,4.803 48.924,5.803 48.924,11.928 49.89,12.893 CELL11.1@49.89,16.921 FB5.1@49.89,18.516
  Bottom Layer w0.3: C21.2@47.924,2.803 P1.5@47.924,4.803
C12: C19.2 CELL12.1 FB4.1 P1.4 | length 14.3
  Top Layer w0.3: P1.4@49.924,7.303 49.924,10.697 52.62,13.393 CELL12.1@52.62,16.921 FB4.1@52.62,18.516
  Bottom Layer w0.3: P1.4@49.924,7.303 C19.2@49.924,9.303
C13: C15.2 CELL13.1 FB3.1 P1.3 | length 18
  Top Layer w0.3: P1.3@49.924,4.803 50.924,5.803 50.924,9.896 55.351,14.323 CELL13.1@55.351,16.921 FB3.1@55.351,18.516
  Bottom Layer w0.3: C15.2@49.924,2.803 P1.3@49.924,4.803
C14: C8.2 CELL14.1 FB2.1 P1.2 R2.1 | length 18.2
  Top Layer w0.3: P1.2@51.924,7.303 51.924,9.03 52.999,10.106 R2.1@57.18,10.106 57.18,11.985 58.081,12.886 CELL14.1@58.081,16.921 FB2.1@58.081,18.516
  Bottom Layer w0.3: P1.2@51.924,7.303 C8.2@51.924,9.303
DIS: Q4.1 R62.2 R76.2 R85.2 TP9.1 U4.6 | length 59.6
  Top Layer w0.3: U4.6@56.922,91.41 56.888,91.377 v1(56.888,90.129) 56.888,89.957 58.06,88.785 R62.2@64.555,88.785
  Layer 2 w0.3: v1(29.556,90.926) 31.139,90.926 34.121,93.909 56.113,93.909 56.888,93.134 v1(56.888,90.129) ; TP9.1@45.075,86.036 47.166,88.127 56.554,88.127 56.888,88.461 v1@56.888,89.957
  Bottom Layer w0.3: R85.2@29.05,90.168 29.187,90.306 Q4.1@29.187,91.856 ; TP9.1@45.075,86.036 R76.2@45.075,88.038
FAULT: D4.1 Q3.1 R75.2 R81.2 TP8.1 U6.3 | length 36.7
  Top Layer w0.3: TP8.1@47.615,86.036 48.2,85.451 U6.3@48.2,79.677 47.942,79.419 v1(47.942,78.827)
  Bottom Layer w0.3: R81.2@32.294,90.168 32.451,90.325 Q3.1@32.451,91.856 34.078,93.483 48.678,93.483 49.434,92.727 49.434,88.369 49.102,88.038 R75.2@47.615,88.038 TP8.1@47.615,86.036 ; v1(47.942,78.827) 48.719,78.827 D4.1@48.96,79.068
FAULTL: GPIO2.1 R39.1 R68.2 U1.11 | length 11.2
  Top Layer w0.3: U1.11@36.441,55.111 v1@36.441,57.071
  Bottom Layer w0.2: GPIO2.1@32.721,63.167 34.498,63.167 R68.2@34.697,62.968 34.552,62.823 34.552,62.577 35.017,62.112 35.017,58.569 35.414,58.172 R39.1@36.373,58.172
  Bottom Layer w0.3: R39.1@36.373,58.172 36.373,57.525 36.566,57.332 v1(36.566,57.264)
GND: C16.1 C77.1 C78.1 C79.1 C80.1 C82.1 C83.2 C84.1 CN3.1 CN3.4 Q3.2 Q4.2 Q5.2 Q6.2 R63.2 R64.1 R65.1 R66.1 R71.1 R81.1 R85.1 R86.1 R87.1 R89.1 TP14.1 TP15.1 U4.13 U5.2
  other v1: 58.389,63.381 60.889,63.381 63.115,63.381 65.615,63.381 67.841,63.38 72.568,63.38 75.068,63.38 75.015,65.246 56.693,67 75.015,67.472 56.694,69.5 75.015,69.698 75.015,72.198 56.694,74.325 75.015,74.424 67.222,74.708 56.694,76.825 75.015,76.924 43.679,77.919 46.179,77.919 50.905,77.919 55.631,77.918 42.606,78.226 75.016,79.15 59.9,79.85 42.606,80.452 59.911,80.677 75.016,81.65 75.016,83.877 58.6,83.95 68,84.45 33.551,84.926 36.051,84.926 38.277,84.926 40.777,84.926 32.017,85.366 75.016,86.377 50.56,86.947 67.1,87.2 32.017,87.866 75.016,88.921 50.56,90.172 67.1,90.35 21.722,91.008 24.99,91.008 28.254,91.008 67.657,94.207 70.157,94.207
GND_BMS: C2.1 C3.1 C4.1 C5.1 C6.1 C7.1 C10.1 C11.1 C12.1 C13.1 C14.1 C22.1 C24.2 C25.2 C26.2 C34.1 C36.2 C37.2 C39.2 C44.1 C47.1 C61.1 C62.1 C63.1 C64.1 C65.1 D1.1 D2.2 D3.1 GND.1 ISOH.SHELL P2.1 P2.2 Q2.2 R10.2 R13.2 R20.2 R32.1 R35.1 R39.2 R43.2 RHOT.1 U1.6 U1.9 U1.22 U1.25 U1.65 U2.2 U3.2 U6.2
  other v1: 7.173,0.603 7.173,2.903 7.173,5.403 0.573,7.903 3.973,7.903 7.173,7.903 0.573,10.403 3.973,10.403 7.173,10.403 0.573,12.903 3.973,12.903 0.573,15.403 3.973,15.403 0.573,17.903 3.973,17.903 0.573,20.403 3.973,20.403 67.166,20.617 70.167,20.617 73.168,20.617 75.138,20.638 12.219,21.217 18.226,21.217 26.662,21.217 32.126,21.217 40.306,21.217 43.038,21.217 51.244,21.217 53.963,21.217 59.525,21.217 62.526,21.217 0.573,22.903 75.071,22.995 6.9,23.287 75.071,25.495 6.9,25.787 75.071,27.995 6.9,28.287 58.634,29.071 32.265,30.037 37.017,30.037 43.226,30.037 47.091,30.037 75.071,30.495 58.634,31.571 75.071,32.995 13.246,33.614 58.634,34.071 75.071,35.495 58.634,36.571 13.246,37.547 75.071,37.995 25.041,38.998 31.557,38.998 35.796,38.998 39.788,38.998 41.404,38.998 43.052,38.998 45.648,38.998 47.292,38.998 58.634,39.071 75.071,40.495 13.246,41.294 58.634,41.571 68.337,41.917 75.071,42.995 68.337,44.417 13.246,44.996 75.071,45.495 25.975,46.879 68.337,46.917 75.071,47.995 13.246,48.905 68.337,49.417 25.5,50.05 75.071,50.495 26.455,52.055 0.573,52.903 75.071,52.995 25.969,53.908 21.801,54.597 19.975,54.618 0.573,55.403 75.071,55.495 26.632,55.56 42.94,55.94 49.128,56.099 47.718,56.107 28.782,57.708 46.018,57.833 0.573,57.903 75.071,57.995 28.755,58.973 32.484,59.001 59.707,59.132 55.805,59.836 58.121,59.864 0.573,60.403 70.071,60.495 72.571,60.495 75.071,60.495 36.25,61.1 53.987,62.274 0.573,62.903 0.573,65.403 25.984,66.385 28.484,66.385 30.984,66.385 53.988,67 0.573,67.903 2.842,67.945 5.342,67.945 7.842,67.945 10.342,67.945 53.988,69.5 41.737,70.039 42.564,70.028 22.738,70.774 25.238,70.774 27.738,70.774 30.238,70.774 32.738,70.774 35.339,70.774 53.988,74.226 41.498,75.269 43.998,75.269 46.224,75.269 48.724,75.269 50.95,75.268 53.45,75.268 39.724,76.965 39.724,79.191 32.977,80.435 34.085,80.435 39.724,81.691 29.018,84.67 29.018,87.17 21.792,87.17 24.292,87.17 26.792,87.17 18.076,89.21 18.076,91.71 5.85,94.21 8.35,94.21 10.85,94.21 13.35,94.21 15.85,94.21 18.076,94.21
  other v2: 33.961,45.804 35.461,45.804 36.961,45.804 38.461,45.804 39.961,45.804 41.433,45.832 33.961,47.304 35.461,47.304 36.961,47.304 38.461,47.304 39.961,47.304 41.461,47.304 33.961,48.804 35.461,48.804 36.961,48.804 38.461,48.804 39.961,48.804 41.461,48.804 33.961,50.304 35.461,50.304 36.961,50.304 38.461,50.304 39.961,50.304 41.461,50.304 33.961,51.804 35.461,51.804 36.961,51.804 38.461,51.804 39.961,51.804 41.461,51.804 33.961,53.304 35.461,53.304 36.961,53.304 38.461,53.304 39.961,53.304 41.461,53.304
GND_EXT: C1.1 C8.1 C15.1 C19.1 C21.1 C29.1 C31.1 C33.1 C40.1 C42.1 C45.1 C48.1 C50.1 C57.1 C59.1 C66.1 C67.1 C68.1 C69.1 C70.1 C71.1 C75.1 C76.1 CGS.1 P1.17 P1.18 P1.22 P1.24 P1.26 P1.28 P1.30 P3.1 P3.2 Q2.3 RHOT.2 RPD.1
  other v1: 22.219,0.502 24.923,0.502 26.946,0.502 28.921,0.502 30.944,0.502 32.967,0.502 35.86,0.502 38.97,0.502 40.917,0.502 42.906,0.502 44.928,0.502 46.938,0.502 48.928,0.502 50.899,0.502 53.661,0.502 56.183,0.502 58.172,0.502 60.195,0.502 62.204,0.502 64.194,0.502 66.165,0.502 68.154,0.502 70.176,0.502 72.186,0.502 20.657,1.407 16.347,3.851 20.657,3.907 16.347,6.351 75.129,6.624 75.129,9.625 33.869,11.829 37.845,11.829 39.576,11.829 41.585,11.829 44.172,11.829 46.267,11.829 47.67,11.829 49.812,11.829 51.946,11.829 75.129,12.626 75.129,15.627 12.185,18.626 14.002,18.628 18.254,18.628 21.247,18.628 23.968,18.628 26.69,18.628 29.413,18.628 32.154,18.628 34.88,18.628 37.625,18.628 40.335,18.628 43.067,18.628 45.808,18.628 48.55,18.628 51.273,18.628 53.992,18.628 56.724,18.628 59.553,18.628 62.554,18.628 64.193,18.628 66.994,18.628 69.995,18.628 72.996,18.628 75.129,18.628
ISENSEM: C76.2 P1.20 R7.1 R61.2 | length 31.7
  Top Layer w0.3: R7.1@16.856,18.578 16.856,14.826 22.338,9.344 33.567,9.344 33.924,8.987 P1.20@33.924,7.303
  Bottom Layer w0.3: R61.2@31.946,12.372 31.511,11.937 31.511,10.886 31.76,10.637 33.094,9.303 C76.2@33.924,9.303 P1.20@33.924,7.303
ISENSEP: C75.2 P1.19 R3.1 R61.1 | length 43.9
  Top Layer w0.3: R3.1@15.131,18.578 15.131,15.63 21.917,8.844 32.596,8.844 32.924,8.516 32.924,5.803 P1.19@33.924,4.803
  Bottom Layer w0.3: R61.1@25.52,12.372 25.09,11.942 25.774,11.259 25.774,10.348 25.985,10.137 30.504,10.137 32.924,7.717 32.924,5.803 P1.19@33.924,4.803 C75.2@33.924,2.803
